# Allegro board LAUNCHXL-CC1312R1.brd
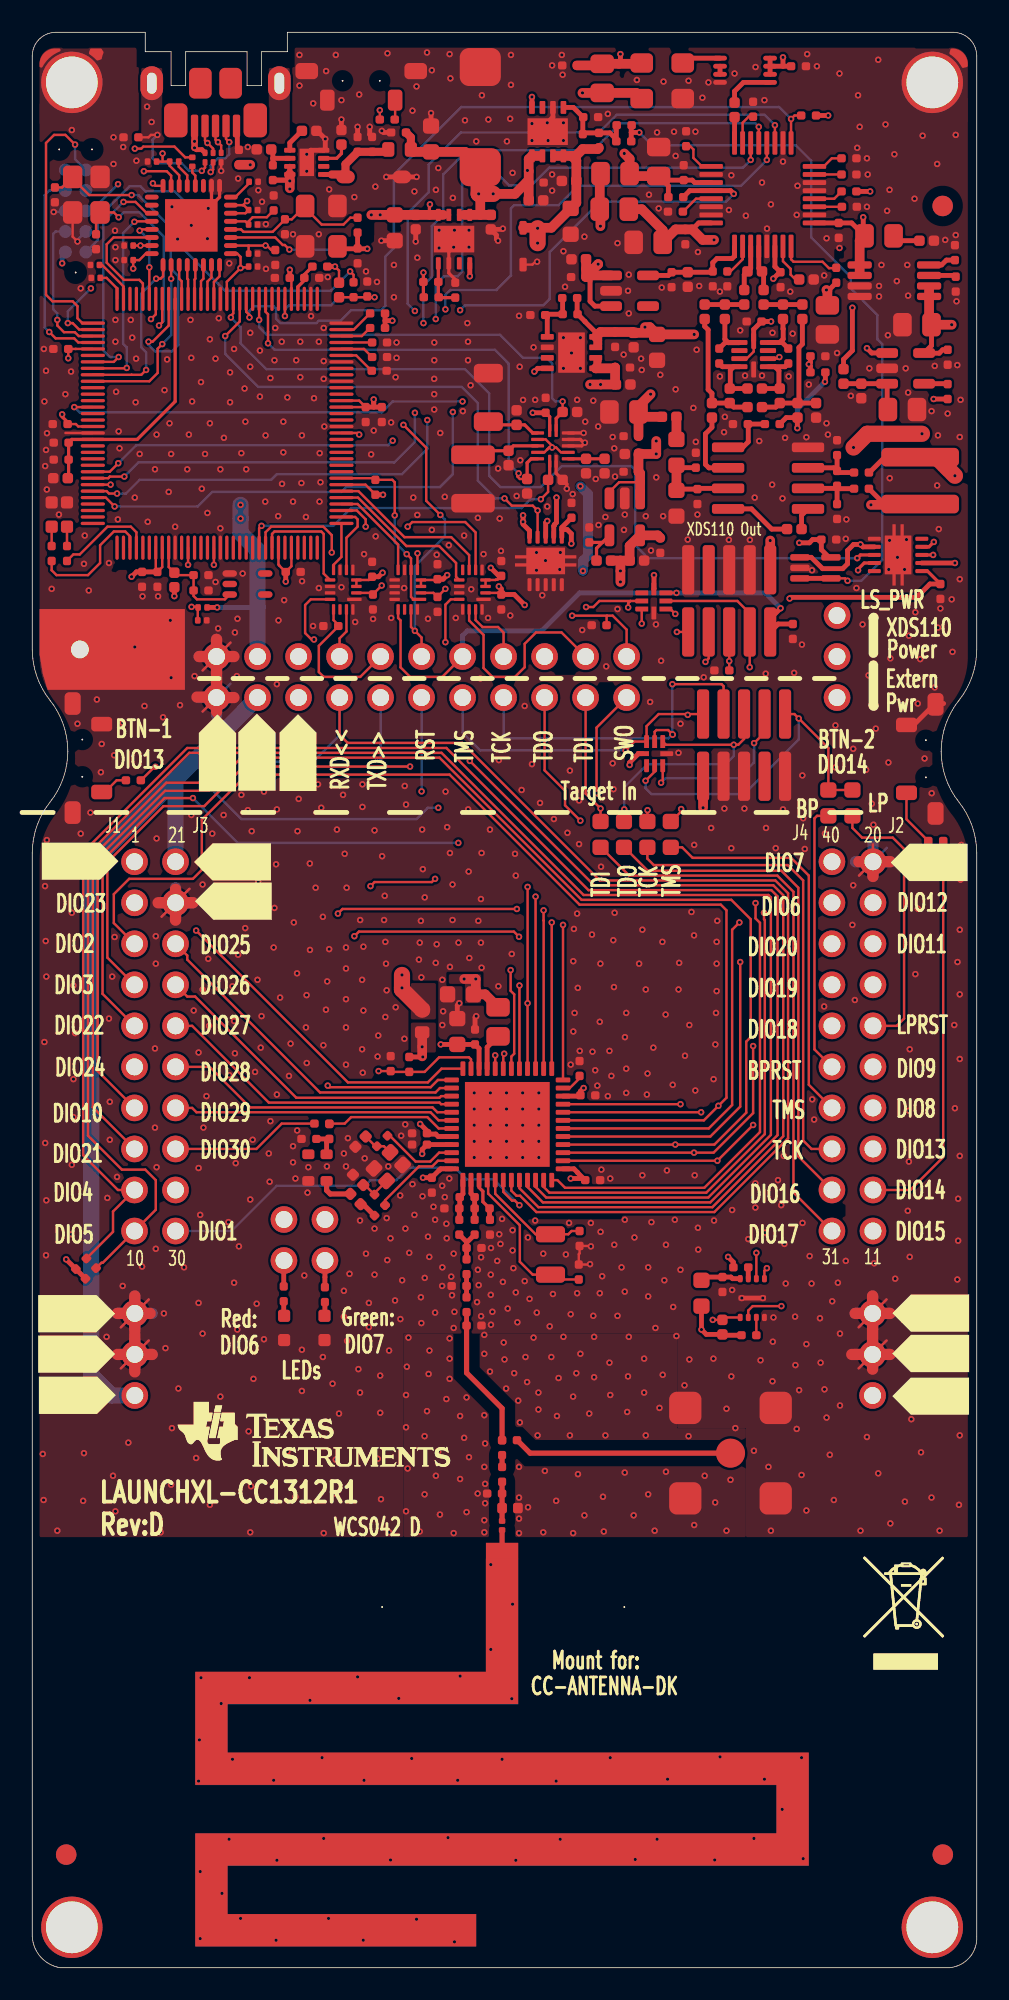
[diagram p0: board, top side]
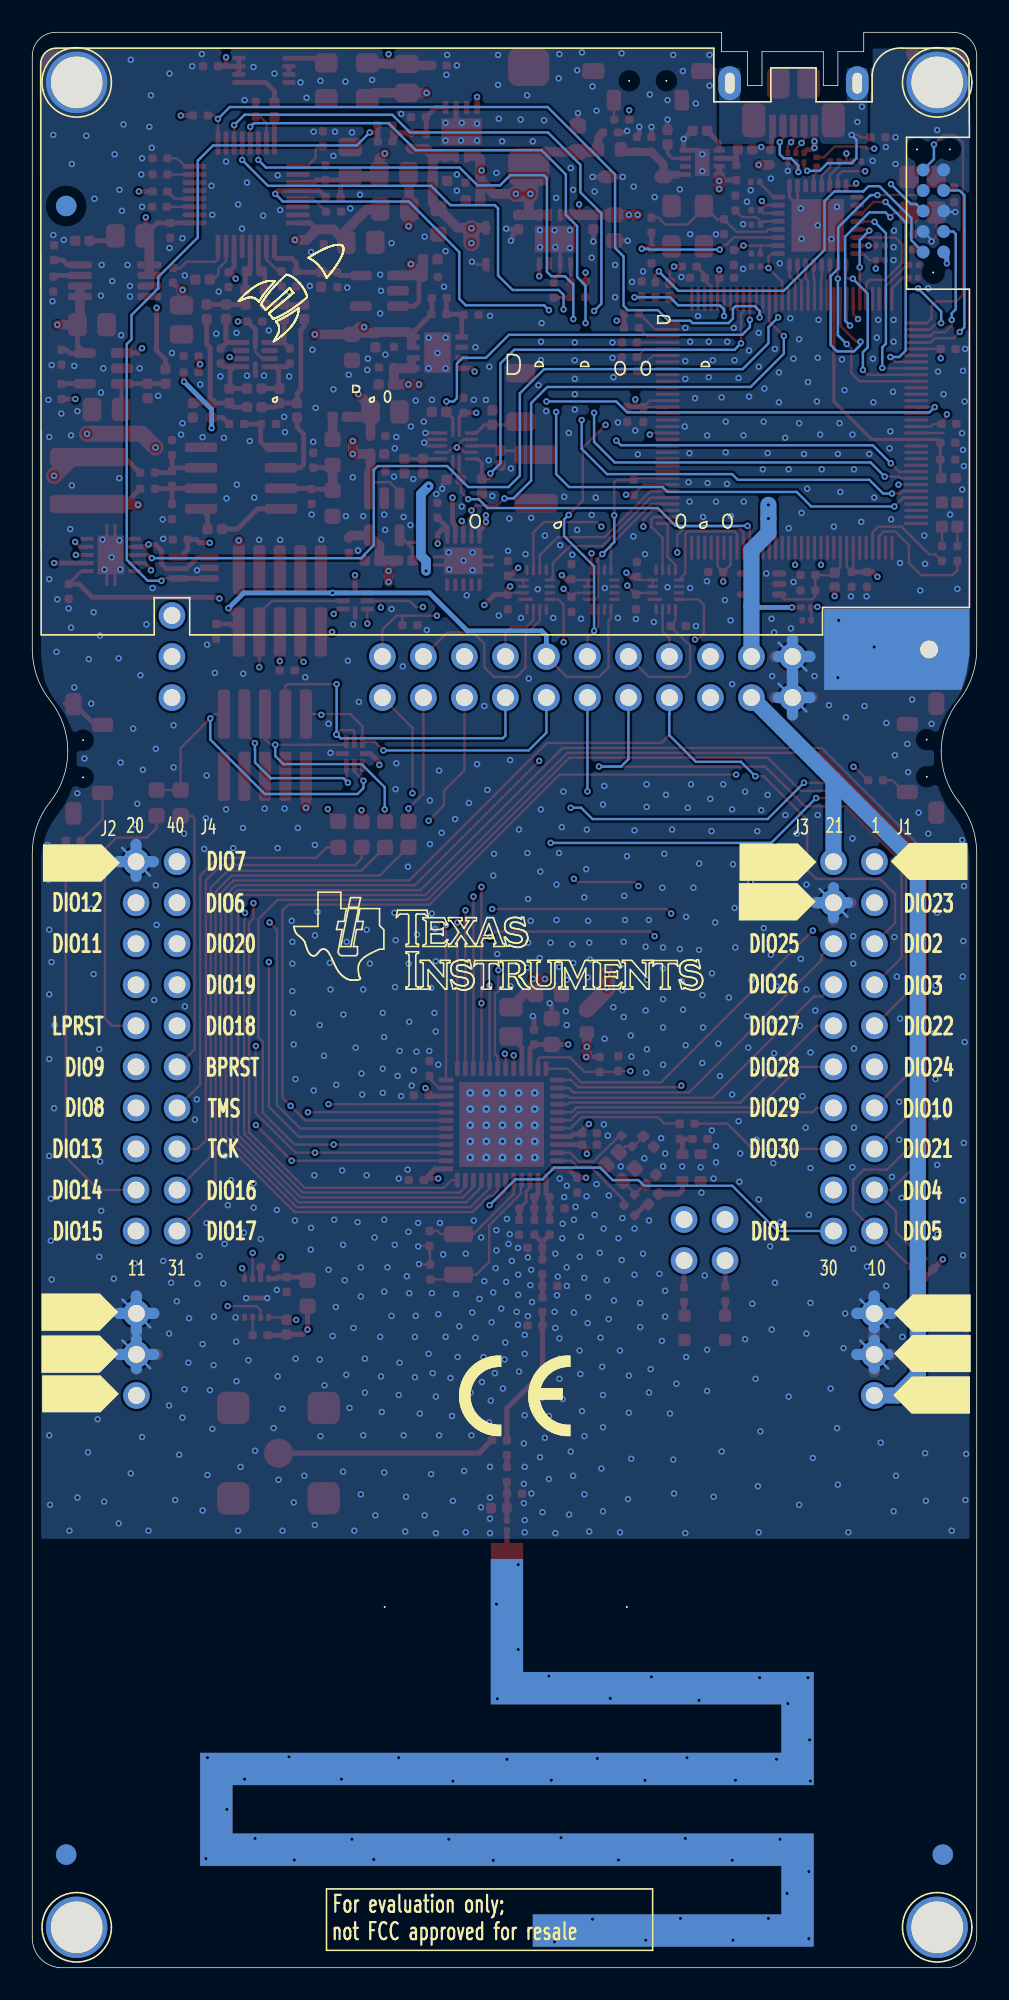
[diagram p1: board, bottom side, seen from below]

Outline 58.5 x 119.8 mm; copper layers: TOP, L2, L3, BOTTOM. Coordinates in mm from the lower left corner of the outline.
Outline path: 0,118.34 0,81.6 arc(0.28,79.93) 1.1,78.45 arc(1.92,76.97) 2.2,75.3 arc(1.92,73.63) 1.1,72.15 arc(0.28,70.67) 0,69 0,1.95 arc(0.51,0.67) 1.72,0 56.8,0 arc(58.05,0.63) 58.5,1.95 58.5,69 arc(58.22,70.67) 57.4,72.15 arc(56.58,73.63) 56.3,75.3 arc(56.58,76.97) 57.4,78.45 arc(58.22,79.93) 58.5,81.6 58.5,118.34 arc(58.07,119.37) 57.04,119.8 15.8,119.8 15.8,118.6 14.2,118.6 14.2,116.5 13.3,116.5 13.3,118.6 9.5,118.6 9.5,116.5 8.6,116.5 8.6,118.6 7,118.6 7,119.8 1.46,119.8 arc(0.43,119.37) 0,118.34

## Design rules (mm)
constraint set DEFAULT: min track width 0.15
nets with their own width: min track width 0.15; nets GND VDDR VDDS WMCU_VDD

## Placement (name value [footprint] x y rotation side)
A1  DNM  [ANTENNA_DN024N]  29.1 25.8 180 top
C1  12pF  [CAPC1005X60B2N]  3.95 107.3 270 top
C2  10nF  [CAPC1005X60B2N]  15.7 86.4 0 top
C3  10nF  [CAPC1005X60B2N]  2.19 95.55 180 top
C4  10nF  [CAPC1005X60B2N]  2.23 100.2 180 top
C6  100nF  [CAPC0603X35B2N]  13.4 105.3 0 top
C7  10nF  [CAPC1005X60B2N]  6.8 86.4 270 top
C8  0.1uF  [CAPC1005X60B2N]  9.99 86.2 0 top
C9  12pF  [CAPC1005X60B2N]  1.4 110.2 270 top
C11  3.6pF  [CAPC1005X60B2N]  26.45 47 180 top
C12  0.1uF  [CAPC1005X60B2N]  34.25 48.75 0 top
C14  0.1uF  [CAPC1005X60B2N]  33.95 54 0 top
C15  0.1uF  [CAPC1005X60B2N]  24.45 51.65 180 top
C16  22uF  [CAPC1608X100A2N]  26.32 57.15 90 top
C17  0.1uF  [CAPC1005X60B2N]  27.42 57.15 90 top
C18  22uF  [CAPC1608X100A2N]  27.32 60.25 180 top
C19  0.1uF  [CAPC1005X60B2N]  24.45 50.95 180 top
C20  0.1uF  [CAPC1005X60B2N]  24.75 48.9 270 top
C21  3.6pF  [CAPC1005X60B2N]  27.4 46.3 270 top
C22  DNM  [CAPC1005X60A2N]  20.5 48.45 135 top
C23  DNM  [CAPC1005X60A2N]  20.65 51.45 225 top
C24  0.1uF  [CAPC1005X60B2N]  17.6 51.3 180 top
C25  1nF  [CAPC1005X60A2N]  19.7 47.9 315 top
C30  0.1uF  [CAPC1005X60B2N]  42.75 42.75 270 top
C31  100pF  [CAPC1005X60B2N]  28.35 46.3 270 top
C33  2.7pF  [CAPC1005X60B2N]  26.9 44.55 0 top
C34  6.2pF  [CAPC1005X60B2N]  26.9 42.2 180 top
C35  3pF  [CAPC1005X60B2N]  26.9 39.75 0 top
C36  100pF  [CAPC1005X60B2N]  29.1 32.65 270 top
C37  DNM  [CAPC1005X60B2N]  29.1 32.65 0 top
C38  0.1uF  [CAPC1005X60B2N]  15.95 104.6 180 top
C39  0.1uF  [CAPC1005X60B2N]  20.65 96.6 270 top
C40  1uF  [CAPC1005X60B2N]  21.65 96.6 270 top
C41  12pF  [CAPC1005X60B2N]  33.85 42.6 90 top
C42  1uF  [CAPC1005X60B2N]  7.75 86.4 270 top
C43  0.1uF  [CAPC1005X60B2N]  2.25 94.4 180 top
C44  1uF  [CAPC1005X60B2N]  2.25 93.35 180 top
C45  2.2uF  [CAPC1005X60A2N]  2.2 92.2 180 top
C46  0.1uF  [CAPC1005X60B2N]  16.85 104.6 0 top
C47  15pF  [CAPC1005X60B2N]  24.25 103.4 0 top
C48  2.2uF  [CAPC1005X60A2N]  28.4 108.5 270 top
C49  2.2uF  [CAPC1005X60A2N]  23.75 108.5 270 top
C50  10nF  [CAPC1005X60B2N]  9.99 85.25 0 top
C51  15pF  [CAPC1005X60B2N]  33.9 45.6 270 top
C52  0.1uF  [CAPC1005X60B2N]  22.2 55.5 90 top
C53  1uF  [CAPC1005X60B2N]  33.9 55.2 90 top
C70  0.1uF  [CAPC1005X60B2N]  21.1 85 270 top
C71  0.1uF  [CAPC1005X60B2N]  21.05 86.1 90 top
C72  0.1uF  [CAPC1005X60B2N]  29.05 85 270 top
C73  0.1uF  [CAPC1005X60B2N]  29.05 86.15 90 top
C74  0.1uF  [CAPC1005X60B2N]  25.1 84.85 270 top
C75  0.1uF  [CAPC1005X60B2N]  25.1 85.95 90 top
C78  100nF  [CAPC0603X35B2N]  6.25 105.7 180 top
C79  100nF  [CAPC0603X35B2N]  13.4 108.8 0 top
C80  100nF  [CAPC0603X35B2N]  7.7 111.8 180 top
C83  100nF  [CAPC0603X35B2N]  13.4 106.1 0 top
C84  100nF  [CAPC0603X35B2N]  6.25 106.6 180 top
C85  4.7uF  [CAPC1005X60B2N]  15.05 105.4 90 top
C86  4.7uF  [CAPC1005X60B2N]  14.95 109.7 270 top
C87  100nF  [CAPC0603X35B2N]  13.4 107.9 0 top
C88  12pF  [CAPC1005X60B2N]  15.65 107.3 90 top
C89  12pF  [CAPC1005X60B2N]  20.15 105.5 90 top
C106  0.1uF  [CAPC1005X60B2N]  12.8 111.6 90 top
C107  33nF  [CAPC1005X60A2N]  16.7 113.7 0 top
C108  10nF  [CAPC1005X60B2N]  21.05 112.4 90 top
C109  1uF  [CAPC1005X60B2N]  20.15 112.4 90 top
C110  0.1uF  [CAPC1005X60B2N]  23.15 113.6 180 top
C111  3.3uF  [CAPC1608X90A2N]  24.7 114 270 top
C112  220uF  [CAPMP7343X430A2N]  27.75 111.45 90 top
C113  22uF  [CAPC1608X100A2N]  22.45 108.5 270 top
C114  0.1uF  [CAPC1005X60B2N]  56.25 85.65 270 top
C115  0.1uF  [CAPC1005X60B2N]  47 117.7 0 top
C116  0.1uF  [CAPC1005X60B2N]  40.35 110.65 90 top
C117  10uF  [CAPC2012X150A2N]  38.8 110.9 90 top
C118  0.1uF  [CAPC1005X60B2N]  33.75 117.75 180 top
C119  0.1uF  [CAPC1005X60B2N]  40.45 107.6 270 top
C120  0.1uF  [CAPC1005X60B2N]  46.35 104.95 270 top
C121  10uF  [CAPC2012X150A2N]  39.05 106.8 180 top
C122  10uF  [CAPC2012X150A2N]  49.25 102.9 270 top
C123  270pF  [CAPC1005X60B2N]  42.55 99.3 90 top
C124  DNM  [CAPC1005X60B2N]  49.85 94.55 270 top
C125  0.1uF  [CAPC1005X60B2N]  41.2 90.6 90 top
C126  0.1uF  [CAPC1005X60B2N]  44.25 101.9 0 top
C127  0.1uF  [CAPC1005X60B2N]  49.95 108 270 top
C128  1uF  [CAPC1005X60B2N]  42.15 105 270 top
C129  470pF  [CAPC1005X60A2N]  44.3 96.6 0 top
C130  1nF  [CAPC1005X60A2N]  44.3 97.75 0 top
C131  22nF  [CAPC1005X60A2N]  44.3 105 0 top
C132  DNM  [CAPC1005X60B2N]  49.85 92.65 270 top
C133  1uF  [CAPC1005X60B2N]  48.2 99.75 0 top
C134  DNM  [CAPC1005X60B2N]  49.85 90.6 270 top
C135  270pF  [CAPC1005X60B2N]  46.83 99.3 90 top
C136  1uF  [CAPC1005X60B2N]  43.05 105 270 top
C137  1uF  [CAPC1005X60B2N]  50.15 109 0 top
C138  1uF  [CAPC1005X60B2N]  40.5 112.75 90 top
C139  0.1uF  [CAPC1005X60B2N]  33.4 89.75 90 top
C140  0.1uF  [CAPC1005X60B2N]  31.8 96.25 90 top
C141  0.1uF  [CAPC1005X60B2N]  56.7 100.15 270 top
C142  10uF  [CAPC2012X150A2N]  55.7 101.7 180 top
C143  2.2uF  [CAPC1005X60A2N]  30 95.5 90 top
C144  2.2uF  [CAPC1005X60A2N]  29.5 93.9 270 top
C145  1uF  [CAPC1005X60B2N]  57.15 105.7 90 top
C146  47uF  [CAPC2012X150A2N]  51.55 107.2 0 top
C147  10uF  [CAPC2012X150A2N]  53 96.45 0 top
C149  2.2uF  [CAPC1005X60A2N]  34.3 93.4 270 top
C151  2.2uF  [CAPC1005X60A2N]  36.15 98 0 top
C152  0.1uF  [CAPC1005X60B2N]  36.1 99.05 0 top
C153  15pF  [CAPC1005X60B2N]  33.75 103.35 180 top
C154  0.1uF  [CAPC1005X60B2N]  36.1 101.25 270 top
C155  2.2uF  [CAPC1005X60A2N]  37.25 101.2 270 top
C156  22uF  [CAPC1608X100A2N]  38.7 101.1 270 top
C157  2.2uF  [CAPC1005X60A2N]  34.3 105.75 180 top
C158  0.1uF  [CAPC1005X60B2N]  39.6 104.95 270 top
C159  2.2uF  [CAPC1005X60A2N]  40.6 104.95 270 top
C160  2.2uF  [CAPC1005X60A2N]  37.6 93.7 180 top
C161  0.1uF  [CAPC1005X60B2N]  37.55 92.6 180 top
C162  0.1uF  [CAPC1005X60B2N]  38.9 88.5 270 top
C163  2.2uF  [CAPC1005X60A2N]  37 87.1 0 top
C164  0.1uF  [CAPC1005X60B2N]  34.3 104.65 180 top
C165  10uF  [CAPC2012X150A2N]  37.55 96.3 180 top
C166  10nF  [CAPC1005X60B2N]  37.55 94.8 180 top
C167  0.1uF  [CAPC1005X60B2N]  41.1 92.85 90 top
C168  22uF  [CAPC1608X100A2N]  39.9 91.45 270 top
C169  DNM  [CAPC1005X60B2N]  36.2 114.05 0 top
C170  DNM  [CAPC1005X60B2N]  49.8 88.4 180 top
C171  2.2uF  [CAPC1005X60A2N]  30.75 109.4 0 top
C172  15pF  [CAPC1005X60B2N]  35.1 112.65 90 top
C173  2.2uF  [CAPC1005X60A2N]  33.7 110.6 180 top
C174  22uF  [CAPC1608X100A2N]  33.35 108.9 270 top
C175  0.1uF  [CAPC1005X60B2N]  30.75 110.5 0 top
CR1  LPL296-J2L2-25  [LEDC1707X65N]  18.1 38.85 90 top
CR2  LS L296-P2Q2-1  [LEDC1708X67N]  15.6 38.85 90 top
CR4  LS L296-P2Q2-1  [LEDC1708X67N]  1.2 90.7 270 top
CR5  LPL296-J2L2-25  [LEDC1707X65N]  2.15 90.7 270 top
CR6  TPD4E004DRY  [SON50P100X145X60-6B2N]  10.7 111.75 0 top
CR7  TPD6E004RSER  [QFN50P150X150X60-8N]  37.75 85.1 270 top
CR8  TPD6E004RSER  [QFN50P150X150X60-8N]  38.05 74.4 0 top
CR14  DNM  [SODFL2512X80A2N]  30.4 107.7 270 top
CR15  NRVB130T1G  [SOD3716X135N]  19.4 110.85 0 top
FIDU1  DNM  [FID127X142]  56.39 109.05 0 top
FIDU2  DNM  [FID127X142]  2.1 7 0 top
FIDU3  DNM  [FID127X142]  56.4 7 0 top
FIDU4  DNM  [FID127X142]  56.4 109.05 180 bottom
FIDU5  DNM  [FID127X142]  2.1 7 180 bottom
FIDU6  DNM  [FID127X142]  56.4 7 180 bottom
FL1  BLM18HE152SN1  [FIL_BLM18HE152SN1DN]  24.15 57.9 90 top
FL2  BLM18HE152SN1  [FIL_BLM18HE152SN1DN]  23.45 112.55 180 top
FL3  BLM18HE152SN1  [FIL_BLM18HE152SN1DN#2]  39.9 93 90 top
FL4  BLM21PG221SN1  [FILC2012X110A2N]  35.3 116.05 90 top
FL5  BLM21PG221SN1  [FILC2012X110A2N]  35.2 111.05 0 top
FL6  BLM21PG221SN1  [FILC2012X110A2N]  36.95 108.85 180 top
J1  SSQ-110-23-L-D  [SAMTEC_SSQ11023LD_A2B]  6.33 68.46 0 bottom
J2  SSQ-110-23-L-D  [SAMTEC_SSQ11023LD_A2B]  49.53 68.46 0 bottom
J6  105164-0001  [MOLEX_1051640001_B2N]  10.05 114 0 top
J7  SMA-10V21-TGG  [HUSTSAN_SMA10V21TGGAN]  43.25 31.85 0 top
L10  6.8uH  [INDC2012X150A2N]  28.85 57.65 90 top
L11  7.5nH  [INDC1005X60D2N]  26.45 46.3 270 top
L12  27nH  [INDC1005X60D2N]  27.4 47.7 180 top
L32  7.5nH  [INDC1005X60D2N]  27.4 47 0 top
L33  6.8nH  [INDC1005X60D2N]  26.9 43.85 270 top
L34  6.8nH  [INDC1005X60D2N]  26.9 41.5 270 top
LBL1  CE_label  [CE_MARKING]  29.45 32.9 180 bottom
LBL2  DNM  [TI_LOGO_1]  10 35.03 0 top
LBL4  DNM  [LABEL_FOR_EVALUATION_ONLY]  40.12 1.22 180 bottom
LBL6  TRASH_7mm  [TRASH_7MM]  52.1 18.45 0 top
M1  SNT-100-BK-G  [SAMTEC_SNT100BKG]  16.88 42.5 90 top
M2  SNT-100-BK-G  [SAMTEC_SNT100BKG]  19.38 42.5 90 top
M3  SNT-100-BK-G  [SAMTEC_SNT100BKG]  12.65 77.3 90 top
M4  SNT-100-BK-G  [SAMTEC_SNT100BKG]  15.25 77.3 90 top
M5  SNT-100-BK-G  [SAMTEC_SNT100BKG]  17.75 77.3 90 top
M6  SNT-100-BK-G  [SAMTEC_SNT100BKG]  20.25 77.3 90 top
M7  SNT-100-BK-G  [SAMTEC_SNT100BKG]  22.85 77.3 90 top
M8  SNT-100-BK-G  [SAMTEC_SNT100BKG]  25.35 77.3 90 top
M9  SNT-100-BK-G  [SAMTEC_SNT100BKG]  27.95 77.3 90 top
M10  SNT-100-BK-G  [SAMTEC_SNT100BKG]  30.45 77.3 90 top
M11  SNT-100-BK-G  [SAMTEC_SNT100BKG]  33.05 77.3 90 top
M12  SNT-100-BK-G  [SAMTEC_SNT100BKG]  35.55 77.3 90 top
M13  SNT-100-BK-G  [SAMTEC_SNT100BKG]  38.15 77.3 90 top
M14  SNT-100-BK-G  [SAMTEC_SNT100BKG]  51.15 79.9 90 top
M15  DCB-10  [MECH_DCB10_A2B]  4.15 4.05 180 bottom
M16  DCB-10  [MECH_DCB10_A2B]  54.5 4 180 bottom
M17  DCB-10  [MECH_DCB10_A2B]  4.25 115 180 bottom
M18  DCB-10  [MECH_DCB10_A2B]  54 114.95 180 bottom
MH1  DNM  [MTG320_380]  2.45 2.5 180 bottom
MH2  DNM  [MTG320_380]  55.75 2.5 180 bottom
MH3  DNM  [MTG320_380]  2.45 116.7 180 bottom
MH4  DNM  [MTG320_380]  55.75 116.7 180 bottom
MH5  DNM  [MTG110_170]  2.95 81.6 0 top
NOREF  -  []  -4.35 67.3 0 top
NOREF#2  -  []  51.55 38.1 0 top
NOREF#3  -  []  -178.4 -140.5 0 top
NOREF#4  -  []  -2.05 32.9 0 top
NOREF#5  -  []  51.45 66 0 top
NOREF#6  -  []  8.35 63.6 0 top
NOREF#7  -  []  -1.95 38.1 0 top
NOREF#8  -  []  -70.48 81.55 0 top
NOREF#9  -  []  -59.23 124.59 0 top
NOREF#10  -  []  56.3 75.34 0 top
NOREF#11  -  []  -1.95 35.6 0 top
NOREF#12  #VALUE  [unnamed#2]  21.67 22.32 0 top
NOREF#13  -  []  -75.31 -10.05 90 top
NOREF#14  -  []  17.65 67.9 90 top
NOREF#15  -  []  58.03 0.61 0 top
NOREF#16  -  []  53.05 34 0 top
NOREF#17  -  []  52.06 0 90 top
NOREF#18  -  []  0.85 -28.78 0 top
NOREF#19  -  []  8.35 65.9 0 top
NOREF#20  -  []  -73.08 125.52 0 top
NOREF#21  -  []  51.55 35.6 0 top
NOREF#22  -  []  16.45 70.4 90 top
NOREF#23  -  []  0 112.17 0 top
NOREF#24  -  []  33.55 35.5 0 top
NOREF#25  -  []  13.85 70.5 90 top
NOREF#26  -  []  6.85 32.9 180 bottom
NOREF#27  -  []  6.85 35.6 180 bottom
NOREF#28  -  []  5.55 67.1 180 bottom
NOREF#29  -  []  6.85 38.1 180 bottom
NOREF#30  -  []  17.05 63.6 180 bottom
NOREF#31  -  []  17.15 65.9 180 bottom
NOREF#32  -  []  51.48 89.52 180 bottom
NOREF#33  -  []  57.95 34.3 180 bottom
NOREF#34  -  []  60.25 38.2 180 bottom
NOREF#35  -  []  60.15 66 180 bottom
NOREF#36  -  []  60.25 35.6 180 bottom
P1  BB02-HC031-KB1-603000  [GRADCONN_BB02HC031KB1603000_A2B]  52.05 35.42 90 top
P2  BB02-HC031-KB1-603000  [GRADCONN_BB02HC031KB1603000_A2B]  6.35 35.42 90 top
P4  BB02-HJ221-KB1-603000  [GRADCONN_BB02HJ221KB160300_A2B]  36.81 81.16 180 top
P5  FTSH-105-01-F-DV-K  [SAMTEC_FTSH10501FDVK_A2N]  41.55 73.75 0 top
P6  BB02-HJ041-KB1-603000  [GRADCONN_BB02HJ041KB1603000_A2B]  15.59 43.77 0 top
P7  FTSH-105-01-F-DV-K  [SAMTEC_FTSH10501FDVK_A2N]  45.71 86.53 180 top
P8  DNM  [TAGCONNECT_TC2050IDCNL_A2N]  2.05 106.2 90 bottom
P10  BB02-HC031-KB1-603000  [GRADCONN_BB02HC031KB1603000_A2B]  49.85 83.7 270 top
PCB1  As Per Fab Drawing-WCS042  [TI_MCUXX]  54.25 30.35 0 top
R1  100k  [RESC1005X40B2N]  23.35 55.45 90 top
R2  3.3k  [RESC1005X40B2N]  3.35 43.9 225 top
R3  3.3k  [RESC1005X40B2N]  3.95 43.3 225 top
R5  0  [RESC1005X40B2N]  21.85 47.2 135 top
R6  0  [RESC1005X40B2N]  22 51.5 225 top
R7  DNM  [RESC1005X40B2N]  21.2 46.55 45 top
R8  DNM  [RESC1005X40B2N]  18.4 51.3 90 top
R9  0  [RESC1005X40B2N]  18.4 52.25 180 top
R11  2.2k  [RESC1005X40A2N]  42.75 39.2 90 top
R12  0  [RESC1608X55A2N]  41.45 42.55 270 top
R14  220  [RESC1005X40B2N]  15.57 41.25 90 top
R15  180  [RESC1005X40B2N]  18.12 41.2 90 top
R17  10k  [RESC1005X40A2N]  19 103.4 90 top
R18  4.7k  [RESC1005X40A2N]  8.8 86.35 270 top
R20  100  [RESC1005X40B2N]  19.9 103.4 90 top
R21  DNM  [RESC1005X40B2N]  20.75 103.45 90 top
R23  180  [RESC1005X40B2N]  1.2 88 270 top
R25  220  [RESC1005X40B2N]  2.15 88 270 top
R27  1k  [RESC1005X40B2N]  21.85 101.5 180 top
R28  4.87k  [RESC1005X40B2N]  21.95 98.85 180 top
R29  1k  [RESC1005X40B2N]  21.05 100.6 0 top
R30  1k  [RESC1005X40B2N]  21.05 99.7 0 top
R31  51  [RESC1005X40B2N]  17.35 105.3 0 top
R32  33k  [RESC1005X40B2N]  5.65 113.3 0 top
R33  51k  [RESC1005X40B2N]  25.15 104.35 180 top
R34  30k  [RESC1005X40B2N]  26.2 104.3 270 top
R39  1k  [RESC1005X40B2N]  21.85 102.4 180 top
R46  DNM  [RESC1608X55A2N]  39.55 69.35 90 top
R47  DNM  [RESC1608X55A2N]  38.1 69.35 90 top
R48  0  [RESC1608X55A2N]  36.65 69.35 90 top
R49  0  [RESC1608X55A2N]  35.2 69.35 90 top
R51  0  [RESC1608X55A2N]  50.8 71.3 90 top
R52  0  [RESC1608X55A2N]  49.31 71.3 90 top
R55  100  [RESC1005X40B2N]  55.5 69.75 0 top
R56  100  [RESC1005X40B2N]  5.8 73.5 0 top
R57  100  [RESC1005X40B2N]  22.45 114.4 180 top
R58  3.3k  [RESC1005X40B2N]  21.25 92.1 270 top
R59  DNM  [RESC1005X40B2N]  44.85 39.15 180 top
R60  DNM  [RESC1005X40B2N]  44.35 43.35 180 top
R61  100k  [RESC1005X40B2N]  18.03 83.05 0 top
R62  100k  [RESC1005X40B2N]  34.65 83.1 0 top
R63  100k  [RESC1005X40B2N]  42.25 80.3 0 top
R65  100k  [RESC1005X40B2N]  47.11 82.25 90 top
R82  10k  [RESC0603X35B2N]  9.91 111.5 90 top
R83  10k  [RESC0603X35B2N]  8.51 111.8 0 top
R84  12k  [RESC0603X35B2N]  13.99 110.55 180 top
R87  1M  [RESC1005X40B2N]  20.15 107.4 90 top
R90  1k  [RESC0603X35B2N]  3.6 105.4 0 top
R91  1k  [RESC0603X35B2N]  3.65 104.6 0 top
R92  10k  [RESC0603X35B2N]  10.27 84.2 0 top
R93  20k  [RESC0603X35B2N]  10.25 83.4 0 top
R94  22  [RESC1005X40A2N]  43.5 114.55 90 top
R95  1.2k  [RESC1005X40A2N]  41.65 102.95 270 top
R96  100k  [RESC1005X40B2N]  48.55 114.65 180 top
R97  100k  [RESC1005X40B2N]  40.3 108.7 180 top
R98  100k  [RESC1005X40B2N]  49.8 104.3 90 top
R99  0  [RESC1005X40B2N]  50.9 92.55 0 top
R100  0  [RESC1005X40B2N]  46.3 95.55 180 top
R101  1.2k  [RESC1005X40A2N]  42.1 96.85 270 top
R102  330  [RESC1005X40A2N]  43.2 97.75 270 top
R103  4.99  [RESC1005X40A2N]  42.9 102.95 270 top
R104  10  [RESC1005X40A2N]  44.1 103.85 270 top
R105  100k  [RESC1005X40B2N]  44.65 115.5 270 top
R106  DNM  [RESC1005X40B2N]  43.4 95.55 0 top
R107  1  [RESC3246X70A2N]  55 93.5 270 top
R108  0  [RESC1005X40B2N]  50.9 91.55 0 top
R109  1.2k  [RESC1005X40A2N]  47.4 96.85 270 top
R110  330  [RESC1005X40A2N]  46.3 97.75 270 top
R111  DNM  [RESC1005X40B2N]  48.2 98.75 0 top
R112  4.99  [RESC1005X40A2N]  46.5 102.95 270 top
R113  10  [RESC1005X40A2N]  45.3 103.85 270 top
R114  100k  [RESC1005X40B2N]  39.4 109.6 0 top
R115  DNM  [RESC1005X40A2N]  48.55 96.85 270 top
R116  60.4k  [RESC1005X40A2N]  48.4 104.5 180 top
R117  100k  [RESC1005X40B2N]  51.05 112 180 top
R118  100k  [RESC1005X40B2N]  51.05 111 180 top
R119  100k  [RESC1005X40B2N]  51.05 109.95 180 top
R120  1.2k  [RESC1005X40A2N]  47.7 102.95 270 top
R121  22k  [RESC1005X40A2N]  50.25 98.95 270 top
R122  0.22  [RESC1005X50A2N]  55.85 106.9 180 top
R123  82  [RESC3216X75A2N]  28.25 98.7 270 top
R125  36.5  [RESC3225X75A2N]  27.3 90.65 90 top
R126  4.7k  [RESC1005X40A2N]  51.35 97.15 90 top
R127  47k  [RESC1005X40A2N]  31.95 92.1 0 top
R128  47k  [RESC1005X40A2N]  30.65 92.15 270 top
R129  47k  [RESC1005X40A2N]  32.85 96.3 0 top
R130  2.2k  [RESC1005X40A2N]  35.45 93.4 270 top
R131  0  [RESC1005X40B2N]  56.7 97.1 90 top
R132  51k  [RESC1005X40B2N]  32.85 102.35 0 top
R133  30k  [RESC1005X40B2N]  30.85 102.3 0 top
R134  60.4k  [RESC1005X40A2N]  34.95 87.1 0 top
R135  30k  [RESC1005X40B2N]  34.5 89.15 270 top
R136  100k  [RESC1005X40B2N]  57.2 103.75 90 top
R137  2.61k  [RESC1005X40A2N]  46.75 89.05 0 top
R138  DNM  [RESC1005X40B2N]  37.1 113.05 180 top
R151  51k  [RESC1005X40B2N]  34.1 113.5 270 top
R152  30k  [RESC1005X40B2N]  35.05 114.55 180 top
R153  10  [RESC1005X40A2N]  39.9 96 180 top
R154  1M  [RESC1005X40B2N]  14.9 110.65 90 top
R155  390k  [RESC1005X40A2N]  13.9 112.55 0 top
R156  4.7k  [RESC1005X40A2N]  19.15 113.75 270 top
SW1  1188E-1K2  [SW_1188E1K2V_A2N]  2.5 78.25 270 top
SW2  1188E-1K2  [SW_1188E1K2V_A2N]  55.95 71.45 90 top
SW3  1188E-1K2  [SW_1188E1K2V_A2N]  23.75 117.4 180 top
U1  CC1312R1F3RGZ  [QFNFC50P700X700X100-49A2N]  26.67 48.75 0 top
U4  MX25R8035FZUIL0  [SON50P300X200X60-9B2N]  43.85 40.25 0 top
U5  TM4C1294NCPDTT3R  [QFP40P1600X1600X120-128N]  5.25 87.9 0 top
U6  LM4040B25IDCK  [SOT65P210X110-5N]  12.23 86.3 270 top
U7  TPS79601DR  [SON65P300X300X100-9AN]  27.1 108.5 180 top
U8  SN74AVC4T245RSV  [QFNFC40P180X260X55-16A2N]  19.95 84.7 90 top
U9  SN74AVC4T245RSV  [QFNFC40P180X260X55-16A2N]  27.95 84.7 90 top
U10  SN74AVC4T245RSV  [QFNFC40P180X260X55-16A2N]  23.95 84.7 90 top
U15  USB3300-EZK  [QFNWB50P500X500X100-33N]  11.6 110.3 180 top
U33  TS3A24159DRC  [SON50P300X300X100-11A2N]  55.1 86.45 90 top
U34  SN74LVC2G74DCU  [SOP50P310X90-8N]  42.6 118.2 270 top
U35  ADS127L01IPBS  [QFP50P700X700X120-32A2N]  43.5 106.55 0 top
U36  INA118UB  [SOIC127P600X175-8A2N]  48.05 90.3 90 top
U37  THS4551IRUN  [QFNFCP50P200X200X80-10A2N]  43.8 100.6 270 top
U38  TS3A24159DRC  [SON50P300X300X100-11A2N]  32.8 88.55 180 top
U39  TS3A4751RUCR  [QFNFC40P200X200X40-14A2N]  31.3 95 270 top
U40  REF6025IDGK  [SOP65P490X110-8A2N]  55.55 103.45 90 top
U41  OPA320AIDBV  [SOT95P280X145-5A2N]  52.95 99.95 270 top
U42  TPS79601DR  [SON65P300X300X100-9AN]  34.9 99 90 top
U43  LP5907MFX-1.8  [SOT95P280X145-5A2N]  35.85 104.75 270 top
U44  TPS73101DBV  [SOT95P280X145-5A2N]  37.65 90.95 180 top
U45  DNM  [SOT65P210X110-5A2N]  47.55 87.3 270 top
U46  TPS79601DR  [SON65P300X300X100-9AN]  30.95 112.15 0 top
U47  TPS259530DSG  [SON50P200X200X80-9A2N]  15.95 112.5 270 top
Y1  32.768kHz  [XTAL_FC135_A2N]  32.1 42.9 90 top
Y2  48MHz  [OSCCC200X160X45-4A2N]  21.95 48.7 45 top
Y3  16MHz  [OSCCC250X320X100-4BN]  2.5 110.85 270 top
Y4  24MHz  [OSCCC250X320X70-4AN]  16.9 109.05 270 top
Y6  16.384MHz  [OSCSC254P320X500X130-4A2N]  37.75 115.7 0 top
Y7  48MHz  [OSC_TG2016SMN_A2N]  17.1 50.35 270 top
Z60  3.3nH  [INDC1005X60B2N]  29.1 31 270 top
Z61  DNM  [CAPC1005X60B2N]  29.1 29.35 180 top
Z62  DNM  [IND_LQW15AN]  29.1 28.45 0 top
Z63  5.6pF  [CAPC0603X35B2N]  29.1 27.65 270 top

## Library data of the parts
A1 = ANTENNA_PCB_0: User Part Number: #PN
C1-C4 C7-C9 C11 C12 C14 C15 C17 C19-C21 C24 C30 C31 C33-C39 C41 C43 C46 C47 C50-C52 C70-C75 C85 C86 C88 C89 C106 C108 C110 C114-C116 C118-C120 C123-C127 C132 C134 C135 C139-C141 C152-C154 C158 C161 C162 C164 C166 C167 C169 C170 C172 C175 Z61 = CAPACITOR: User Part Number: #PN
C6 C78-C80 C83 C84 C87 Z63 = CAPACITOR: User Part Number: #PN; alternate symbols: (CAPC0603X35B2L,CAPC0603X35B2M)
C16 C18 C113 C156 C168 C174 = CAPACITOR: User Part Number: #PN; alternate symbols: (CAPC1608X100A2L,CAPC1608X100A2M)
C22 C23 C25 C40 C42 C44 C45 C48 C49 C53 C107 C109 C128-C131 C133 C136-C138 C143-C145 C149 C151 C155 C157 C159 C160 C163 C171 C173 = CAPACITOR: User Part Number: #PN; alternate symbols: (CAPC1005X60A2L,CAPC1005X60A2M)
C111 = CAPACITOR: User Part Number: #PN; alternate symbols: (CAPC1608X90A2L,CAPC1608X90A2M)
C112 = CAPACITOR_POL_8: User Part Number: #PN; alternate symbols: (CAPMP7343X430A2L,CAPMP7343X430A2M)
C117 C121 C122 C142 C146 C147 C165 = CAPACITOR: User Part Number: #PN; alternate symbols: (CAPC2012X150A2L,CAPC2012X150A2M)
CR1 CR5 = LED_0: alternate symbols: (LEDC1707X65L,LEDC1707X65M)
CR2 CR4 = LED_0: alternate symbols: (LEDC1708X67L,LEDC1708X67M)
CR6 = DIODE_TVS_TPD4E004_SON6: User Part Number: #PN; alternate symbols: (SON50P100X145X65-6L,SON50P100X145X65-6M)
CR7 CR8 = DIODE_TVS_TPD6E004_QFN8_V1: alternate symbols: (QFN50P150X150X60-8L,QFN50P150X150X60-8M)
CR14 = DIODE_ZENER_1: User Part Number: #PN; alternate symbols: (SODFL2512X80A2L,SODFL2512X80A2M)
CR15 = DIODE_SCHOTTKY_2: alternate symbols: (SOD3716X135L,SOD3716X135M,SOD3716X135BN)
FIDU1-FIDU6 = FIDMARK
FL1-FL3 = FILTER_2PIN: alternate symbols: (FIL_BLM18HE152SN1DL,FIL_BLM18HE152SN1DM)
FL4 = INDUCTOR_3: User Part Number: #PN; alternate symbols: (FILC2012X110A2L,FILC2012X110A2M)
FL5 = INDUCTOR_4: User Part Number: #PN; alternate symbols: (FILC2012X110A2L,FILC2012X110A2M)
FL6 = INDUCTOR_5: User Part Number: #PN; alternate symbols: (FILC2012X110A2L,FILC2012X110A2M)
J1 J2 = CONN_HEADER_2X10_J_S_V1: User Part Number: #PN; alternate symbols: (SAMTEC_SSQ11023LD_A2C,SAMTEC_SSQ11023LD_A2A)
J6 = CONN_USB_MICRO_B_2MH: User Part Number: #PN; alternate symbols: (MOLEX_1051640001_B2L,MOLEX_1051640001_B2M)
J7 = CONN_COAX_1_4: alternate symbols: (HUSTSAN_SMA10V21TGGL,HUSTSAN_SMA10V21TGGM)
L10 = INDUCTOR_4: User Part Number: #PN; alternate symbols: (INDC2012X150A2L,INDC2012X150A2M)
L11 L32-L34 = INDUCTOR_HOR_1_1: User Part Number: #PN
L12 = INDUCTOR_HOR_1_0: User Part Number: #PN
LBL1 = CE_LABEL_V1
LBL2 = TI_LOGO_V1
LBL4 = LABEL_FOR_EVALUATOIN_ONLY: User Part Number: #PN
LBL6 = TRASH_V2: User Part Number: #PN
M1-M14 = MECH_SHUNT_JUMPER_V1: User Part Number: #PN
M15-M18 = MECH_SPACERS_SUPPORT_V1: User Part Number: #PN
MH1-MH5 = HOLE_PTH
NOREF#12 = -: User Part Number: #PN
P1 P2 P10 = CONN_HEADER_3_P_S: User Part Number: #PN; alternate symbols: (GRADCONN_BB02HC031KB1603000_A2C,GRADCONN_BB02HC031KB1603000_A2A)
P4 = CONN_HEADER_2X11_P_S: User Part Number: #PN; alternate symbols: (GRADCONN_BB02HJ221KB160300_A2C,GRADCONN_BB02HJ221KB160300_A2A)
P5 P7 = CONN_HEADER_2X5: User Part Number: #PN; alternate symbols: (SAMTEC_FTSH10501FDVK_A2L,SAMTEC_FTSH10501FDVK_A2M)
P6 = CONN_HEADER_2X2_P: User Part Number: #PN; alternate symbols: (GRADCONN_BB02HJ041KB1603000_A2C,GRADCONN_BB02HJ041KB1603000_A2A)
P8 = CONN_IDC_TC2050-IDC-NL: User Part Number: #PN; alternate symbols: (TAGCONNECT_TC2050IDCNL_A2L,TAGCONNECT_TC2050IDCNL_A2M)
PCB1 = PCB_V2: User Part Number: #PN
R1-R3 R5-R9 R14 R15 R20 R21 R23 R25 R27-R34 R39 R55-R63 R65 R87 R96-R100 R105 R106 R108 R111 R114 R117-R119 R131-R133 R135 R136 R138 R151 R152 R154 = RESISTOR: User Part Number: #PN
R11 R17 R18 R94 R95 R101-R104 R109 R110 R112 R113 R115 R116 R120 R121 R126-R130 R134 R137 R153 R155 R156 = RESISTOR: alternate symbols: (RESC1005X40A2L,RESC1005X40A2M)
R12 R46-R49 R51 R52 = RESISTOR: User Part Number: #PN; alternate symbols: (RESC1608X55A2L,RESC1608X55A2M)
R82-R84 R90-R93 = RESISTOR: User Part Number: #PN; alternate symbols: (RESC0603X35B2L,RESC0603X35B2M)
R107 = RESISTOR: User Part Number: #PN; alternate symbols: (RESC3246X70A2L,RESC3246X70A2M)
R122 = RESISTOR: User Part Number: #PN; alternate symbols: (RESC1005X50A2L,RESC1005X50A2M)
R123 = RESISTOR: User Part Number: #PN; alternate symbols: (RESC3216X75A2L,RESC3216X75A2M)
R125 = RESISTOR: User Part Number: #PN; alternate symbols: (RESC3225X75A2L,RESC3225X75A2M)
SW1-SW3 = SWITCH_TACT_V2: alternate symbols: (SW_1188E1K2V_A2L,SW_1188E1K2V_A2M)
U1 = IC_RF_CC1312R1F3_VQFN48: User Part Number: #PN; alternate symbols: (QFNFC50P700X700X100-49A2L,QFNFC50P700X700X100-49A2M)
U4 = IC_FLASH_MX25R8035F_USON8: User Part Number: #PN; alternate symbols: (SON50P300X200X60-9B2L,SON50P300X200X60-9B2M)
U5 = IC_PROC_TM4C1294NCPDT_TQFP128: alternate symbols: (QFP40P1600X1600X120-128L,QFP40P1600X1600X120-128M)
U6 = IC_REF_LM4040_SC70-5: alternate symbols: (SOT65P210X110-5L,SOT65P210X110-5M)
U7 U42 U46 = IC_PM_TPS79601_SON8: alternate symbols: (SON65P300X300X100-9AL,SON65P300X300X100-9AM)
U8-U10 = IC_XCVR_SN74AVC4T245_UQFN16_2: User Part Number: #PN; alternate symbols: (QFNFC40P180X260X55-16A2L,QFNFC40P180X260X55-16A2M)
U15 = IC_PROC_USB3300_QFN32: alternate symbols: (QFNWB50P500X500X100-33L,QFNWB50P500X500X100-33M,QFNWB50P500X500X100-33DL,QFNWB50P500X500X100-33DM)
U33 U38 = IC_SWITCH_TS3A24159_SON10: User Part Number: #PN; alternate symbols: (SON50P300X300X100-11A2L,SON50P300X300X100-11A2M)
U34 = IC_LOGIC_SN74LVC2G74_VSSOP8: alternate symbols: (SOP50P310X90-8L,SOP50P310X90-8M)
U35 = IC_ADC_ADS127L01_QFP32_0: User Part Number: #PN; alternate symbols: (QFP50P700X700X120-32A2L,QFP50P700X700X120-32A2M)
U36 = IC_OPAMP_INA118U_SO8: User Part Number: #PN; alternate symbols: (SOIC127P600X175-8A2L,SOIC127P600X175-8A2M)
U37 = IC_OPAMP_THS4551_QFN10: User Part Number: #PN; alternate symbols: (QFNFCP50P200X200X80-10A2L,QFNFCP50P200X200X80-10A2M)
U39 = IC_SWITCH_TS3A4751_QFN14: User Part Number: #PN; alternate symbols: (QFNFC40P200X200X40-14A2L,QFNFC40P200X200X40-14A2M)
U40 = IC_REF_REF6025_VSSOP8: User Part Number: #PN; alternate symbols: (SOP65P490X110-8A2L,SOP65P490X110-8A2M)
U41 = IC_OPAMP_OPA320_SOT23-5: User Part Number: #PN; alternate symbols: (SOT95P280X145-5A2L,SOT95P280X145-5A2M)
U43 = IC_PM_LP5907-1_8_SOT23-5: User Part Number: #PN; alternate symbols: (SOT95P280X145-5A2L,SOT95P280X145-5A2M)
U44 = IC_PM_TPS73101_SOT23-5: User Part Number: #PN; alternate symbols: (SOT95P280X145-5A2L,SOT95P280X145-5A2M)
U45 = IC_OPAMP_OPA314_SC70-5: User Part Number: #PN; alternate symbols: (SOT65P210X110-5A2L,SOT65P210X110-5A2M)
U47 = IC_PM_TPS259530_WSON8: alternate symbols: (SON50P200X200X80-9A2L,SON50P200X200X80-9A2M)
Y1 = CRYSTAL: User Part Number: #PN; alternate symbols: (XTAL_FC135_A2L,XTAL_FC135_A2M)
Y2 = XTAL_4PINS_1_3: User Part Number: #PN; alternate symbols: (OSCCC200X160X45-4A2L,OSCCC200X160X45-4A2M)
Y3 = XTAL_4: alternate symbols: (OSCCC250X320X100-4BL,OSCCC250X320X100-4BM)
Y4 = XTAL_4: alternate symbols: (OSCCC250X320X70-4AL,OSCCC250X320X70-4AM)
Y6 = XTAL_GEN_EN_V1: User Part Number: #PN; alternate symbols: (OSCSC254P320X500X130-4A2L,OSCSC254P320X500X130-4A2M)
Y7 = XTAL_GEN_V2: User Part Number: #PN; alternate symbols: (OSC_TG2016SMN_A2L,OSC_TG2016SMN_A2M)
Z60 = INDUCTOR_4: User Part Number: #PN
Z62 = INDUCTOR_4: alternate symbols: (IND_LQW15AL,IND_LQW15AM)

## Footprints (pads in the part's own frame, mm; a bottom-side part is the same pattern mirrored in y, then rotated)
ANTENNA_DN024N
  rect 2x1 smd: 1(0,0)
CAPC0603X35B2N
  custom 0.087x0.087 smd: 1(0,0) 2(0.56,0)
CAPC1005X60A2N
  custom 0.16x0.16 smd: 1(0,0) 2(0.9,0)
CAPC1005X60B2N
  custom 0.125x0.125 smd: 1(0,0) 2(0.924,0)
CAPC1608X90A2N
  custom 0.237x0.237 smd: 1(0,0) 2(1.6,0)
CAPC1608X100A2N
  custom 0.237x0.237 smd: 1(0,0) 2(1.6,0)
CAPC2012X150A2N
  custom 0.287x0.287 smd: 1(0,0) 2(1.8,0)
CAPMP7343X430A2N
  custom 0.588x0.588 smd: 1(0,0) 2(6.2,0)
FID127X142
  round 1.27 smd: 1(0,0)
FIL_BLM18HE152SN1DN
  custom 0.188x0.188 smd: 1(0,0) 2(1.4,0)
FIL_BLM18HE152SN1DN#2
  custom 0.237x0.237 smd: 1(0,0) 2(1.6,0)
FILC2012X110A2N
  custom 0.287x0.287 smd: 1(0,0) 2(1.8,0)
GRADCONN_BB02HC031KB1603000_A2B
  round 1.65 hole 1.05: 1(0,0) 2(2.54,0) 3(5.08,0)
GRADCONN_BB02HJ041KB1603000_A2B
  round 1.65 hole 1.05: 1(0,0) 2(0,2.54) 3(2.54,0) 4(2.54,2.54)
GRADCONN_BB02HJ221KB160300_A2B
  round 1.65 hole 1.05: 1(0,0) 2(0,2.54) 3(2.54,0) 4(2.54,2.54) 5(5.08,0) 6(5.08,2.54) 7(7.62,0) 8(7.62,2.54) 9(10.16,0) 10(10.16,2.54) 11(12.7,0) 12(12.7,2.54) 13(15.24,0) 14(15.24,2.54) 15(17.78,0) 16(17.78,2.54) 17(20.32,0) 18(20.32,2.54) 19(22.86,0) 20(22.86,2.54) 21(25.4,0) 22(25.4,2.54)
HUSTSAN_SMA10V21TGGAN
  round 1.8 smd: 1(0,0)
  custom 0.5x0.5 smd: 2(-2.8,-2.8) 3(2.8,-2.8) 4(2.8,2.8) 5(-2.8,2.8)
IND_LQW15AN
  custom 0.15x0.15 smd: 1(0,0) 2(0.98,0)
INDC1005X60B2N
  custom 0.125x0.125 smd: 1(0,0) 2(0.924,0)
INDC1005X60D2N
  custom 0.125x0.125 smd: 1(0,0) 2(0.924,0)
INDC2012X150A2N
  custom 0.287x0.287 smd: 1(0,0) 2(1.8,0)
LEDC1707X65N
  custom 0.188x0.188 smd: 1(0,0) 2(1.501,0)
LEDC1708X67N
  custom 0.188x0.188 smd: 1(0,0) 2(1.501,0)
MOLEX_1051640001_B2N
  custom 0.362x0.362 smd: (-1.162,0.35) (3.762,0.35)
  custom 0.35x0.35 smd: (0.362,2.65) (2.238,2.65)
  custom 0.113x0.113 smd: 1(0,0) 2(0.65,0) 3(1.3,0) 4(1.95,0) 5(2.6,0)
  oval 1.4x2.1 hole 0.6x1.3: M1(-2.65,2.65) M2(5.25,2.65)
MTG110_170
  round 1.699 hole 1.1: 1(0,0)
MTG320_380
  round 3.8 hole 3.2: 1(0,0)
OSC_TG2016SMN_A2N
  custom 0.15x0.15 smd: 1(0,0) 2(1.65,0) 3(1.65,1.13) 4(0,1.13)
OSCCC200X160X45-4A2N
  custom 0.2x0.2 smd: 1(0,0) 2(1.4,0) 3(1.4,1.1) 4(0,1.1)
OSCCC250X320X70-4AN
  custom 0.287x0.287 smd: 1(0,0) 2(2.5,0) 3(2.5,2) 4(0,2)
OSCCC250X320X100-4BN
  custom 0.299x0.299 smd: 1(0,0) 2(2.2,0) 3(2.2,1.699) 4(0,1.699)
OSCSC254P320X500X130-4A2N
  custom 0.3x0.3 smd: 1(0,0) 2(2.54,0) 3(2.54,2.2) 4(0,2.2)
QFN50P150X150X60-8N
  custom 0.075x0.075 smd: 1(0,0) 2(0.5,0) 3(1,0) 4(1.25,0.75) 5(1,1.5) 6(0.5,1.5) 7(0,1.5) 8(-0.25,0.75)
QFNFC40P180X260X55-16A2N
  custom 0.05x0.05 smd: 1(0,0) 2(0.4,-0.125) 3(0.8,-0.125) 4(1.2,-0.125) 5(1.825,0.09) 6(1.825,0.49) 7(1.825,0.89) 8(1.825,1.29) 9(1.2,1.505) 10(0.8,1.505) 11(0.4,1.505) 12(0,1.505) 13(-0.625,1.29) 14(-0.625,0.89) 15(-0.625,0.49) 16(-0.625,0.09)
QFNFC40P200X200X40-14A2N
  custom 0.05x0.05 smd: 1(0,0) 2(0.4,0) 3(0.8,0) 4(1.2,0) 5(1.6,0) 6(1.75,0.75) 7(1.75,1.15) 8(1.6,1.9) 9(1.2,1.9) 10(0.8,1.9) 11(0.4,1.9) 12(0,1.9) 13(-0.15,1.15) 14(-0.15,0.75)
QFNFC50P700X700X100-49A2N
  custom 0.075x0.075 smd: 1(0,0) 2(0.5,0) 3(1,0) 4(1.5,0) 5(2,0) 6(2.5,0) 7(3,0) 8(3.5,0) 9(4,0) 10(4.5,0) 11(5,0) 12(5.5,0) 13(6.2,0.7) 14(6.2,1.2) 15(6.2,1.7) 16(6.2,2.2) 17(6.2,2.7) 18(6.2,3.2) 19(6.2,3.7) 20(6.2,4.2) 21(6.2,4.7) 22(6.2,5.2) 23(6.2,5.7) 24(6.2,6.2) 25(5.5,6.9) 26(5,6.9) 27(4.5,6.9) 28(4,6.9) 29(3.5,6.9) 30(3,6.9) 31(2.5,6.9) 32(2,6.9) 33(1.5,6.9) 34(1,6.9) 35(0.5,6.9) 36(0,6.9) 37(-0.7,6.2) 38(-0.7,5.7) 39(-0.7,5.2) 40(-0.7,4.7) 41(-0.7,4.2) 42(-0.7,3.7) 43(-0.7,3.2) 44(-0.7,2.7) 45(-0.7,2.2) 46(-0.7,1.7) 47(-0.7,1.2) 48(-0.7,0.7)
  rect 5.25x5.25 smd: 49(2.75,3.45)
QFNFCP50P200X200X80-10A2N
  custom 0.075x0.075 smd: 1(0,0) 2(0.5,0) 3(1,0) 4(1.5,0) 5(1.67,0.885) 6(1.5,1.77) 7(1,1.77) 8(0.5,1.77) 9(0,1.77) 10(-0.1,0.885)
QFNWB50P500X500X100-33N
  oval 0.3x0.851 smd: 1(0,0) 2(0.5,0) 3(1,0) 4(1.5,0) 5(2,0) 6(2.5,0) 7(3,0) 8(3.5,0) 17(3.5,4.9) 18(3,4.9) 19(2.5,4.9) 20(2,4.9) 21(1.5,4.9) 22(1,4.9) 23(0.5,4.9) 24(0,4.9)
  oval 0.851x0.3 smd: 9(4.2,0.7) 10(4.2,1.2) 11(4.2,1.7) 12(4.2,2.2) 13(4.2,2.7) 14(4.2,3.2) 15(4.2,3.7) 16(4.2,4.2) 25(-0.7,4.2) 26(-0.7,3.7) 27(-0.7,3.2) 28(-0.7,2.7) 29(-0.7,2.2) 30(-0.7,1.7) 31(-0.7,1.2) 32(-0.7,0.7)
  rect 3.25x3.25 smd: 33(1.75,2.45)
QFP40P1600X1600X120-128N
  oval 0.201x1.501 smd: 1(0,0) 2(0.399,0) 3(0.8,0) 4(1.199,0) 5(1.6,0) 6(1.999,0) 7(2.4,0) 8(2.799,0) 9(3.2,0) 10(3.599,0) 11(4,0) 12(4.399,0) 13(4.801,0) 14(5.199,0) 15(5.601,0) 16(6,0) 17(6.401,0) 18(6.8,0) 19(7.201,0) 20(7.6,0) 21(8.001,0) 22(8.4,0) 23(8.801,0) 24(9.2,0) 25(9.601,0) 26(10,0) 27(10.399,0) 28(10.8,0) 29(11.199,0) 30(11.6,0) 31(11.999,0) 32(12.4,0) 65(12.4,15.4) 66(11.999,15.4) 67(11.6,15.4) 68(11.199,15.4) 69(10.8,15.4) 70(10.399,15.4) 71(10,15.4) 72(9.601,15.4) 73(9.2,15.4) 74(8.801,15.4) 75(8.4,15.4) 76(8.001,15.4) 77(7.6,15.4) 78(7.201,15.4) 79(6.8,15.4) 80(6.401,15.4) 81(6,15.4) 82(5.601,15.4) 83(5.199,15.4) 84(4.801,15.4) 85(4.399,15.4) 86(4,15.4) 87(3.599,15.4) 88(3.2,15.4) 89(2.799,15.4) 90(2.4,15.4) 91(1.999,15.4) 92(1.6,15.4) 93(1.199,15.4) 94(0.8,15.4) 95(0.399,15.4) 96(0,15.4)
  oval 1.501x0.201 smd: 33(13.899,1.501) 34(13.899,1.9) 35(13.899,2.301) 36(13.899,2.7) 37(13.899,3.099) 38(13.899,3.5) 39(13.899,3.899) 40(13.899,4.3) 41(13.899,4.699) 42(13.899,5.1) 43(13.899,5.499) 44(13.899,5.9) 45(13.899,6.299) 46(13.899,6.7) 47(13.899,7.099) 48(13.899,7.501) 49(13.899,7.899) 50(13.899,8.301) 51(13.899,8.7) 52(13.899,9.101) 53(13.899,9.5) 54(13.899,9.901) 55(13.899,10.3) 56(13.899,10.701) 57(13.899,11.1) 58(13.899,11.501) 59(13.899,11.9) 60(13.899,12.301) 61(13.899,12.7) 62(13.899,13.099) 63(13.899,13.5) 64(13.899,13.899) 97(-1.501,13.899) 98(-1.501,13.5) 99(-1.501,13.099) 100(-1.501,12.7) 101(-1.501,12.301) 102(-1.501,11.9) 103(-1.501,11.501) 104(-1.501,11.1) 105(-1.501,10.701) 106(-1.501,10.3) 107(-1.501,9.901) 108(-1.501,9.5) 109(-1.501,9.101) 110(-1.501,8.7) 111(-1.501,8.301) 112(-1.501,7.899) 113(-1.501,7.501) 114(-1.501,7.099) 115(-1.501,6.7) 116(-1.501,6.299) 117(-1.501,5.9) 118(-1.501,5.499) 119(-1.501,5.1) 120(-1.501,4.699) 121(-1.501,4.3) 122(-1.501,3.899) 123(-1.501,3.5) 124(-1.501,3.099) 125(-1.501,2.7) 126(-1.501,2.301) 127(-1.501,1.9) 128(-1.501,1.501)
QFP50P700X700X120-32A2N
  custom 0.075x0.075 smd: 1(0,0) 2(0.5,0) 3(1,0) 4(1.5,0) 5(2,0) 6(2.5,0) 7(3,0) 8(3.5,0) 9(4.95,1.45) 10(4.95,1.95) 11(4.95,2.45) 12(4.95,2.95) 13(4.95,3.45) 14(4.95,3.95) 15(4.95,4.45) 16(4.95,4.95) 17(3.5,6.4) 18(3,6.4) 19(2.5,6.4) 20(2,6.4) 21(1.5,6.4) 22(1,6.4) 23(0.5,6.4) 24(0,6.4) 25(-1.45,4.95) 26(-1.45,4.45) 27(-1.45,3.95) 28(-1.45,3.45) 29(-1.45,2.95) 30(-1.45,2.45) 31(-1.45,1.95) 32(-1.45,1.45)
RESC0603X35B2N
  custom 0.087x0.087 smd: 1(0,0) 2(0.56,0)
RESC1005X40A2N
  custom 0.16x0.16 smd: 1(0,0) 2(0.9,0)
RESC1005X40B2N
  custom 0.125x0.125 smd: 1(0,0) 2(0.924,0)
RESC1005X50A2N
  custom 0.16x0.16 smd: 1(0,0) 2(0.9,0)
RESC1608X55A2N
  custom 0.237x0.237 smd: 1(0,0) 2(1.6,0)
RESC3216X75A2N
  custom 0.287x0.287 smd: 1(0,0) 2(3,0)
RESC3225X75A2N
  custom 0.287x0.287 smd: 1(0,0) 2(3,0)
RESC3246X70A2N
  custom 0.287x0.287 smd: 1(0,0) 2(2.9,0)
SAMTEC_FTSH10501FDVK_A2N
  custom 0.188x0.188 smd: 1(0,0) 2(0,3.85) 3(1.27,0) 4(1.27,3.85) 5(2.54,0) 6(2.54,3.85) 7(3.81,0) 8(3.81,3.85) 9(5.08,0) 10(5.08,3.85)
SAMTEC_SSQ11023LD_A2B
  round 1.65 hole 1.05: 1(0,0) 2(2.54,0) 3(0,2.54) 4(2.54,2.54) 5(0,5.08) 6(2.54,5.08) 7(0,7.62) 8(2.54,7.62) 9(0,10.16) 10(2.54,10.16) 11(0,12.7) 12(2.54,12.7) 13(0,15.24) 14(2.54,15.24) 15(0,17.78) 16(2.54,17.78) 17(0,20.32) 18(2.54,20.32) 19(0,22.86) 20(2.54,22.86)
SOD3716X135N
  oval 1.15x0.8 smd: 1(0,0) 2(3.5,0)
SODFL2512X80A2N
  custom 0.113x0.113 smd: 1(0,0) 2(2.28,0)
SOIC127P600X175-8A2N
  custom 0.15x0.15 smd: 1(0,0) 2(1.27,0) 3(2.54,0) 4(3.81,0) 5(3.81,4.95) 6(2.54,4.95) 7(1.27,4.95) 8(0,4.95)
SON50P100X145X60-6B2N
  custom 0.075x0.075 smd: 1(0,0) 2(0.5,0) 3(1,0) 4(1,0.59) 5(0.5,0.59) 6(0,0.59)
SON50P200X200X80-9A2N
  custom 0.075x0.075 smd: 1(0,0) 2(0.5,0) 3(1,0) 4(1.5,0) 5(1.5,2.1) 6(1,2.1) 7(0.5,2.1) 8(0,2.1)
  rect 1.7x0.9 smd: 9(0.75,1.05)
SON50P300X200X60-9B2N
  custom 0.075x0.075 smd: 1(0,0) 2(0.5,0) 3(1,0) 4(1.5,0) 5(1.5,2.4) 6(1,2.4) 7(0.5,2.4) 8(0,2.4)
  rect 1.7x0.3 smd: 9(0.75,1.2)
SON50P300X300X100-11A2N
  custom 0.062x0.062 smd: 1(0,0) 2(0.5,0) 3(1,0) 4(1.5,0) 5(2,0) 6(2,2.94) 7(1.5,2.94) 8(1,2.94) 9(0.5,2.94) 10(0,2.94)
  custom 0.412x0.412 smd: 11(1,1.47)
SON65P300X300X100-9AN
  custom 0.075x0.075 smd: 1(0,0) 2(0.65,0) 3(1.3,0) 4(1.95,0) 5(1.95,3) 6(1.3,3) 7(0.65,3) 8(0,3)
  rect 2.5x1.65 smd: 9(0.975,1.5)
SOP50P310X90-8N
  oval 0.3x0.851 smd: 1(0,0) 2(0.5,0) 3(1,0) 4(1.5,0) 5(1.5,3.1) 6(1,3.1) 7(0.5,3.1) 8(0,3.1)
SOP65P490X110-8A2N
  custom 0.113x0.113 smd: 1(0,0) 2(0.65,0) 3(1.3,0) 4(1.95,0) 5(1.95,4.3) 6(1.3,4.3) 7(0.65,4.3) 8(0,4.3)
SOT65P210X110-5A2N
  custom 0.1x0.1 smd: 1(0,0) 2(0.65,0) 3(1.3,0) 4(1.3,1.92) 5(0,1.92)
SOT65P210X110-5N
  oval 0.399x0.899 smd: 1(0,0) 2(0.65,0) 3(1.3,0) 4(1.3,2.2) 5(0,2.2)
SOT95P280X145-5A2N
  custom 0.15x0.15 smd: 1(0,0) 2(0.95,0) 3(1.9,0) 4(1.9,2.29) 5(0,2.29)
SW_1188E1K2V_A2N
  round 0.099 hole 0.899 unplated: (2.229,0.6) (4.529,0.6)
  custom 0.25x0.25 smd: 1(0,0) 2(6.75,0)
  custom 0.225x0.225 smd: 3(1.275,1.8) 4(5.475,1.8)
TAGCONNECT_TC2050IDCNL_A2N
  round 0.1 hole 1 unplated: (-1.27,0.635) (6.35,-0.38) (6.35,1.65)
  round 0.8 smd: 1(0,0) 2(1.27,0) 3(2.54,0) 4(3.81,0) 5(5.08,0) 6(5.08,1.27) 7(3.81,1.27) 8(2.54,1.27) 9(1.27,1.27) 10(0,1.27)
unnamed#2
  round 0.099 hole 3.2 unplated: (0,0) (15,0)
XTAL_FC135_A2N
  custom 0.25x0.25 smd: 1(0,0) 2(2.5,0)

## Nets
5V0: C48.1 C110.1 C111.2 C112.1 C151.1 C152.1 C157.1 C160.1 C161.1 C164.1 C165.1 C166.1 C171.1 C175.1 FL2.1 P4.19 R82.2 R92.2 R153.2 U7.1 U7.2 U7.8 U42.1 U42.2 U42.8 U43.1 U43.3 U44.1 U44.3 U46.1 U46.2 U46.8
5V0_BP: J1.2 P2.1 P4.20
GND: C1.2 C2.2 C3.2 C4.2 C6.2 C7.2 C8.2 C9.2 C11.2 C12.2 C14.2 C15.2 C16.2 C17.2 C18.2 C19.2 C20.2 C22.2 C23.2 C24.2 C30.2 C31.2 C33.2 C34.2 C35.2 C38.2 C39.2 C40.2 C41.2 C42.2 C43.2 C44.2 C45.2 C46.2 C48.2 C49.2 C50.2 C51.2 C52.2 C53.2 C70.2 C71.2 C72.2 C73.2 C74.2 C75.2 C78.2 C79.2 C80.2 C83.2 C84.2 C85.1 C86.1 C87.2 C88.1 C89.1 C106.2 C107.2 C108.2 C109.2 C110.2 C111.1 C112.2 C113.2 C114.2 C115.2 C116.2 C117.2 C118.2 C119.2 C120.2 C121.2 C122.2 C124.1 C125.1 C126.1 C127.2 C128.2 C133.2 C134.2 C136.2 C137.2 C138.2 C139.2 C140.2 C141.2 C142.2 C143.2 C144.2 C145.2 C147.2 C149.2 C151.2 C152.2 C154.2 C155.2 C156.2 C157.2 C158.2 C159.2 C160.2 C161.2 C162.2 C163.2 C164.2 C165.2 C166.2 C167.2 C168.2 C170.1 C171.2 C173.2 C174.2 C175.2 CR1.1(C) CR2.1(C) CR4.1(C) CR5.1(C) CR6.3 CR7.4 CR8.4 CR14.2 CR15.2 J1.4 J2.2 J6.5 J7.2 J7.3 J7.4 J7.5 MH3.1 MH4.1 MH5.1 P1.2 P1.3 P2.2 P2.3 P4.21 P4.22 P5.3 P5.5 P5.9 P7.3 P7.5 P7.9 P8.3 P8.5 P8.9 R21.2 R28.1 R29.2 R30.2 R32.1 R34.1 R61.1 R62.1 R63.1 R65.1 R84.1 R90.1 R91.1 R93.2 R97.2 R105.1 R106.1 R115.2 R116.1 R117.1 R118.1 R122.1 R123.1 R125.1 R126.1 R127.2 R128.2 R129.2 R130.2 R133.1 R135.1 R136.1 R152.1 R155.1 R156.1 SW1.1 SW1.2 SW1.3 SW2.1 SW2.2 SW2.4 SW3.1 SW3.2 SW3.4 U1.49 U4.4 U4.9 U5.10 U5.17 U5.48 U5.55 U5.58 U5.64 U5.66 U5.80 U5.114 U6.1 U7.6 U7.9 U8.1 U8.5 U8.7 U8.10 U8.11 U8.16 U9.1 U9.5 U9.10 U9.11 U9.13 U9.16 U10.7 U10.9 U10.10 U10.11 U10.12 U10.16 U15.1 U15.2 U15.33 U33.6 U33.11 U34.4 U35.5 U35.10 U35.13 U35.14 U35.18 U35.26 U35.30 U35.31 U36.4(V-) U37.5(VS-) U38.6 U38.7 U38.8 U38.9 U38.10 U38.11 U39.7 U39.10 U39.11 U39.12 U40.7 U40.8 U41.2(V-) U42.6 U42.9 U43.2 U44.2 U45.2(V-) U46.6 U46.9 U47.8 U47.9 Y2.2 Y2.4(GND#4) Y3.2 Y3.4 Y4.2 Y4.4 Y6.2 Y7.2 Z61.2 Z62.2
VBUS_DET: R92.1 R93.1 U5.12
VDDC: C43.1 C44.1 C45.1 U5.87(VDDC#87) U5.115
VDDR: C18.1 C19.1 C20.1 L10.2 U1.45 U1.48
VDDS: C12.1 C14.1 C15.1 C16.1 C17.1 FL1.1 R1.2 U1.13 U1.22 U1.34 U1.44
BP_RESET: J2.11 R52.1
DCDC_SW: L10.1 U1.33
DIO1: J1.20 U1.6
DIO4_SCL: J1.17 R2.1 U1.9
DIO5_SDA: J1.19 R3.1 U1.10
DIO6_RLED: J2.3 P6.2 U1.11
DIO7_GLED: J2.1 P6.4 U1.12
DIO8_MISO: J2.14 U1.14 U4.2
DIO9_MOSI: J2.12 U1.15(DIO_9) U4.5
DIO10_SCLK: J1.13 U1.16 U4.6
DIO11_CS: J2.6 U1.17
DIO12: J2.4 U1.18
DIO13_BTN1: J2.16 R56.2 U1.19
DIO14_BTN2: J2.18 R55.2 U1.20
DIO15: J2.20 U1.21
DIO16_TDO: CR8.5 P4.6 P5.6 R48.2 U1.26
DIO17_TDI: CR8.3 P4.4 P5.8 R49.2 U1.27
DIO19_CTS: J2.7 U1.29
DIO20_FLASH_CS: J2.5 R11.2 U1.30 U4.1
DIO21: J1.15 U1.31
DIO22: J1.9 U1.32
DIO23_ANALOG: J1.3 U1.36
DIO24_ANALOG: J1.11 U1.37
DIO25_ANALOG: J1.6 U1.38
DIO26_ANALOG: J1.8 U1.39
DIO27_ANALOG: J1.10 U1.40
DIO28_ANALOG: J1.12 U1.41
DIO29_ANALOG: J1.14 U1.42
DIO30/TCXO_VCC: R8.2 R9.1 U1.43
DIO30_ANALOG: J1.16 R9.2
ET_1V8: C128.1 C158.1 C159.1 U35.1 U43.5(OUT)
ET_3V3: C126.2 C141.1 C142.1 C153.1 C154.1 C155.1 C156.1 FL5.1 FL6.2 R132.2 U37.3 U37.10 U40.1(VIN) U40.2 U41.5 U42.3 U42.4(OUT#4)
ET_5V0: C125.2 C167.1 C168.1 FL3.1 U36.7
ET_AVDD: C119.1 C120.1 C121.1 C122.1 FL6.1 R98.1 U35.6 U35.32
ET_BYPASS: U5.78 U33.4 U33.8
ET_CAL0: R129.1 U5.74 U39.13
ET_CAL1: R128.1 U5.73 U39.5
ET_CAL2: R127.1 U5.23 U39.6
ET_CALIBRATE: U5.77 U38.4
ET_DVDD: C116.1 C117.1 FL4.1 FL5.2 R96.1 R114.1 R119.1 U35.27 Y6.1
ET_FB: C169.2 R138.1 U45.3 U45.4
ET_PM2: R96.2 U5.76 U35.17(START)
ET_PN3: R114.2 U5.110 U35.28
ET_SSICLK: U5.120 U35.22
ET_SSIDAT0: U5.123 U35.21
ET_SSIDAT1: U5.124 U35.20
ET_SSIFSS: U5.121 U35.19
ET_VDD: C172.1 C173.1 C174.1 CR14.1(CATHODE) P10.1 R151.2 U46.3 U46.4(OUT#4)
ET_VREF: C127.1 C146.1 R121.1 U35.9 U40.5 U40.6
IRSTN: P8.10 R20.2
ITCK: P8.4 U5.100
ITDI: P8.8 U5.98
ITDO: P8.6 U5.97
ITMS: P8.2 U5.99
LP_RESET: J2.10 R51.1
LS_VDD: C70.1 C72.1 C74.1 CR7.8(VCC) P7.1 P10.2 U8.2(VCCB) U9.2(VCCB) U10.2(VCCB) U33.3 U33.9
SW_VDD: C114.1 C139.1 C140.1 C162.1 C163.1 C170.2 R134.2 U33.1(VCC) U38.1(VCC) U39.14(VCC) U44.5(OUT) U45.5
TARGET_VDD: P4.17 U38.5
TCXO_OUTPUT: C25.2 R7.1
USB1V8: C83.1 C84.1 C85.2 U15.15 U15.26
USB_VBUS: C106.1 CR6.6(VCC) J6.1(VCC) R154.1 U47.3 U47.4
USBA1V8: C86.2 C87.1 U15.29
USBCLK: U5.92 U15.14
USBD0: U5.81 U15.24
USBD1: U5.82 U15.23
USBD2: U5.83 U15.22
USBD3: U5.84 U15.21
USBD4: U5.85 U15.20
USBD5: U5.86 U15.19
USBD6: U5.106 U15.18
USBD7: U5.105 U15.17
USBDIR: U5.104 U15.12
USBDM: CR6.5 J6.2 U15.8
USBDP: CR6.4 J6.3 U15.7
USBNXT: U5.103 U15.11
USBSTP: U5.91 U15.13
VCM: R100.1 R109.2 R111.2 R131.1 U41.1
WMCU_RESET: C52.1 CR8.2 P4.12 P5.10 R1.1 R51.2 R52.2 U1.35
WMCU_RXD: J1.5 P4.16 U1.7
WMCU_SWO: J2.9 P4.2 U1.28
WMCU_TCK: CR8.6 P4.8 P5.4 R47.2 U1.25
WMCU_TMS: CR8.7 P4.10 P5.2 R46.2 U1.24
WMCU_TXD: J1.7 P4.14 U1.8
WMCU_VDD: CR8.8(VCC) FL1.2 J1.1 P1.1 P4.18 P5.1 P10.3 R2.2 R3.2 R11.1 R12.2 R59.2 R60.2
XDS_RESET: R58.1 U5.40 U10.1 U10.6
XDS_RESET_LS: CR7.2 P4.11 P7.10 R57.2 U10.15
XDS_RX: U5.33 U8.8
XDS_RX_LS: P4.13 R61.2 U8.13
XDS_SWO: U5.25 U8.9
XDS_SWO_LS: P4.1 R62.2 U8.12
XDS_TCK: U5.35 U9.6
XDS_TCK_LS: CR7.6 P4.7 P7.4 U9.15
XDS_TDI: U5.38 U9.7
XDS_TDI_LS: CR7.3 P4.3 P7.8 U9.14
XDS_TDO: U5.37 U9.9
XDS_TDO_LS: CR7.5 P4.5 P7.6 R63.2 U9.12
XDS_TMS: U5.36 U10.8
XDS_TMS_DIR: U5.24 U10.5
XDS_TMS_LS: CR7.7 P4.9 P7.2 R65.2 U10.13
XDS_TX: U5.34 U8.6
XDS_TX_LS: P4.15 U8.15
XDS_VDD: C2.1 C3.1 C4.1 C6.1 C7.1 C38.1 C39.1 C40.1 C42.1 C47.1 C49.1 C71.1 C73.1 C75.1 C78.1 C79.1 C80.1 C113.1 P8.1 R17.2 R18.2 R27.1 R31.2 R33.2 R39.1 R58.2 R83.1 U5.7 U5.8 U5.16 U5.26 U5.28 U5.39 U5.47 U5.51 U5.52 U5.69 U5.79 U5.90 U5.101 U5.113 U5.122 U7.3 U7.4(OUT#4) U8.3 U8.4 U9.3 U9.4 U10.3 U10.4 U15.6 U15.16 U15.25 U15.30 U15.31
N949215: R17.1 R20.1 R21.1 U5.70
N949243: R30.1 U5.60
N949263: C47.2 R33.1 R34.2 U7.5
N949375: R28.2 U5.59
N949687: C1.1 U5.89 Y3.3
N949699: C9.1 U5.88 Y3.1
N950083: C8.1 C50.1 R18.1 U5.9 U6.3
N951001: R39.2 U5.63
N951013: R29.1 U5.61
N951017: R27.2 U5.62
N952443: C46.1 R31.1 U5.68
N1004371: R23.2 U5.3
N1004534: R25.2 U5.4
N1014101: C41.1 U1.4 Y1.1
N1014113: C51.1 U1.5 Y1.2
N1017630: C30.1 R12.1 U4.8(VCC)
N1018954: C22.1 R5.2 Y2.1
N1031635: CR6.1 J6.M1 J6.M2 R32.2
N1105722: CR1.2 R15.1
N1105771: CR2.2 R14.1
N1105824: P6.1 R14.2
N1106228: P6.3 R15.2
N1176548: J2.15 R47.1
N1176568: J2.17 R48.1
N1177007: J2.19 R49.1
N1288065: R55.1 SW2.3
N1288098: R56.1 SW1.4
N1384129: R57.1 SW3.3
N1409884: R59.1 U4.3
N1409917: R60.1 U4.7
N1553941: R83.2 U15.5
N1579665: R84.2 U15.32
N1580179: C88.2 R87.2 U15.28 Y4.1
N1580186: C89.2 R87.1 U15.27(XO) Y4.3
N1644260: R90.2 U5.95
N1644363: R91.2 U5.96
N2070550: C53.1 U1.23
N2071733: C11.1 L11.1 L12.2 U1.1
N2072219: C21.1 L12.1 L32.1 U1.2
N2074535: C31.1 L32.2 U1.3
N2075216: C21.2 C33.1 L11.2 L33.1
N2075665: C34.1 L33.2 L34.1
N2076038: C35.1 C36.1 C37.1 L34.2
N2078765: C37.2 J7.1
N2082297: Z60.2 Z61.1 Z62.1 Z63.1
N2239551: R5.1 R7.2 U1.47
N2239563: R6.1 U1.46
N2245591: A1.1 Z63.2
N2266542: C36.2 Z60.1
N3002303: C115.1 C118.1 FL4.2 U34.6 U34.7 U34.8(VCC) Y6.4(VCC)
N3002611: R99.2 R107.1 U33.2
N3002631: U34.1 Y6.3
N3002671: U34.2 U34.3
N3002679: R94.2 U34.5
N3002683: R94.1 U35.24
N3002707: R107.2 R108.2 U33.7 U38.3 U45.1
N3002889: C129.1 R95.2 R101.1 R102.2
N3002897: R95.1 R103.1 R104.2
N3003137: C123.1 C130.1 R102.1 U37.4
N3003145: C123.2 R103.2 U37.1
N3003349: R97.1 U35.29
N3003461: C124.2 C132.1 R99.1 U36.3
N3003521: R98.2 U35.8
N3003585: R137.1 U36.8
N3003709: R101.2 U36.6
N3003761: C131.1 R104.1 U35.3
N3003773: R105.2 U35.23
N3003833: C132.2 C134.1 R108.1 U36.2
N3003845: C133.1 R111.1 U37.7
N3003889: R100.2 R106.2 U36.5
N3003929: C130.2 C135.1 R110.1 U37.6
N3003937: C135.2 R112.2 U37.9
N3003989: C136.1 U35.2
N3004061: C129.2 R109.1 R110.2 R115.1 R120.2
N3004137: C131.2 R113.1 U35.4
N3004141: C137.1 U35.11
N3004269: R112.1 R113.2 R120.1
N3004289: C138.1 U35.25
N3004389: R116.2 U35.7
N3004561: R117.2 U35.16
N3004593: R118.2 U35.15
N3004681: R119.2 U35.12
N3004851: U38.2 U39.2 U39.4 U39.9
N3005293: C143.1 R123.2 U39.1
N3005369: R136.2 U40.3
N3005381: C147.1 R121.2 R126.2 U41.3
N3005457: C145.1 U40.4
N3005465: C146.2 R122.2
N3005509: C144.1 R125.2 U39.3
N3005629: R131.2 U41.4
N3005723: C149.1 R130.1 U39.8
N3011605: C153.2 R132.1 R133.2 U42.5
N3011753: C169.1 C172.2 R138.2 R151.1 R152.2 U46.5
N3012529: R134.1 R135.2 U44.4
N3025885: R137.2 U36.1
N3156339: FL3.2 R153.1
N3157182: C23.1 R6.2 Y2.3
N3167465: C108.1 C109.1 CR15.1(CATHODE) FL2.2 U47.5(OUT)
N3174121: CR6.2 J6.4
N3220034: J2.13 R46.1
N3261415: R154.2 R155.2 U47.2
N3263468: C107.1 U47.1
N3266724: R156.2 U47.7
N3270349: R82.1 U15.4
N3291381: C25.1 Y7.3
N3291400: C24.1 R8.1 Y7.4(VCC)
N10367920: CR5.2 R25.1
N10368080: CR4.2 R23.1

Pads without a net: CR7 1; CR8 1; FIDU1 1; FIDU2 1; FIDU3 1; FIDU4 1; FIDU5 1; FIDU6 1; J1 18; J2 8; MH1 1; MH2 1; P5 7; P7 7; P8 7; U5 1 2 5 6 11 13 14 15 18 19 20 21 22 27 29 30 31 32 41 42 43 44 45 46 49 50 53 54 56 57 65 67 71 72 75 93 94 102 107 108 109 111 112 116 117 118 119 125 126 127 128; U6 2 4 5; U7 7; U8 14; U9 8; U10 14; U15 3 9 10; U33 5 10; U37 2 8; U42 7; U43 4; U46 7; U47 6; Y7 1

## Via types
v1: diameter 0.4, hole 0.2, TOP to BOTTOM, 1369 vias
v2: diameter 0.5, hole 0.201, TOP to BOTTOM, 25 vias

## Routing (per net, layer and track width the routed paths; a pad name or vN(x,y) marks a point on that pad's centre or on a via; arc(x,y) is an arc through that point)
5V0: length 154.1
  TOP w0.15: U44.3 35.75,91.35 36.35,91.95 37.65,91.95 ; R82.2 9.47,112.06 8.81,112.73 6.88,112.73 6.75,112.6 v1(6.35,112.6)
  TOP w0.3: 26.75,108.5 U7.2 ; v1(31.1,98.8) 31.3,99 U42.8 ; U43.3 34.85,102.85 34.55,103.15 34.55,104.4 C164.1 ; v1(30.67,111.25) 30.7,111.25 30.75,111.2 ; R92.2 v1(11.45,84.2) ; U7.8 v1(27.1,104.7) ; 34.9,99 35.1,99.2 35.1,99.45 35.1,99.45 U42.2 U42.1 ; U46.8 v1(30.95,115.8) ; 31.45,112.15 U46.2
  TOP w0.5: C110.1 23.45,113.3 FL2.1
  TOP w0.6: 34.3,105.15 34.75,105.15 35.05,105.45 v1(35.05,105.45) ; 34.3,105.15 C157.1 ; 34.3,105.15 C164.1 34.4,104.75 U43.1 ; v1(38.3,97.4) 37.55,96.65 C165.1 ; FL2.1 23.6,112.4 C111.2 26.8,112.4 C112.1 27.65,111.35 ; C160.1 37.55,93.65 C161.1 37.65,92.5 U44.1 ; C160.1 37.55,93.75 ; C160.1 v1(38.65,93.7) v1(38.65,94.5) ; 27.75,108.5 27.75,109.7 v1(27.65,109.8) ; 27.75,108.5 U7.1 26.75,108.5 ; 27.75,108.5 C48.1 28.4,108.5 ; R153.2 37.85,96 C165.1 ; C171.1 C175.1 ; C175.1 30.75,111.95 U46.1 31.45,112.15 ; C175.1 30.6,110.5 29.9,109.8 v1(28.55,109.8) ; C165.1 C166.1 ; U42.1 36.05,99 C152.1 36.1,98.05 C151.1 v1(35.2,98) v1(34.55,98)
  TOP w1: v1(28.55,109.8) v1(27.65,109.8) 27.65,111.35
  L3 w0.15: v1(6.35,112.6) 6.35,113.8 7.45,114.9 19.91,114.9 20.81,115.8 25.37,115.8 26.07,115.1 26.07,113.7 27.67,112.1 27.67,109.82 v1(27.65,109.8)
  L3 w0.3: v1(30.67,111.25) 30.23,111.69 30.23,115.5 30.53,115.8 v1(30.95,115.8) ; v1(34.55,98) 31.18,98 31.11,97.93 31.1,97.94 v1(31.1,98.8) ; v1(27.1,104.7) 27.91,104.7
  L3 w0.6: v1(38.65,93.7) 38.63,93.7 ; 38.16,97.4 v1(38.3,97.4) ; v1(35.05,105.45) 34.49,105.45 33.74,104.7 27.91,104.7 ; v1(34.55,98) 34.6,97.95 ; v1(38.65,94.5) 38.63,94.5
  L3 w1: 29.91,97.93 29.53,97.93 24.4,92.8 15.15,92.8 v1(12.9,90.55) v1(12.9,89.7) ; 29.91,97.93 27.91,99.93 27.91,108.74 28.55,109.38 v1(28.55,109.8) v1(27.65,109.8) ; 29.91,97.93 34.7,97.93 34.71,97.93 34.71,97.93 37.63,97.93 38.63,96.93 38.63,93.7
  BOTTOM w0.3: 13.95,84.25 13.9,84.2 v1(11.45,84.2)
  BOTTOM w1: v1(12.9,90.55) v1(12.9,89.7) 12.9,88.8 13.95,87.75 P4.19
5V0_BP: length 54.5
  BOTTOM w1: P4.20 8.87,73.54 ; 8.87,73.54 3.65,68.32 3.65,36.67 4.9,35.42 P2.1 ; 8.87,73.54 J1.2
GND: length 302.9
  TOP w0.15: 7.21,38.82 P2.2 5.49,37.1 ; 12.27,82.02 P4.21 10.55,80.3 ; 52.07,69.54 J2.2 51.21,67.6 ; v1(34.55,43.55) 34.52,43.52 C41.2 33.85,44.16 33.9,44.21 C51.2 34.57,44.68 v1(34.6,44.65) ; 51.19,37.1 P1.2 52.91,38.82 ; 11.41,82.24 11.41,82.22 ; 8.01,65.06 J1.4 9.73,66.78 ; 3.75,95 2.05,95 ; 11.41,77.54 11.41,77.75 ; v1(31.27,105.6) 31.16,105.6 30.98,105.42 CR14.2 ; v1(18.75,29.35) 18.65,29.35 ; Y3.2 2.5,107.15 v1(2.8,106.85) ; 7.21,41.36 P2.3 5.49,39.64 ; 52.05,36.88 52.05,37.05 ; 10.55,77.76 P4.22 10.34,78.62 ; 51.19,39.64 P1.3 52.91,41.36 ; 51,68.46 51.2,68.46 ; 7.43,40.5 7.3,40.5 ; v1(11.7,111.22) CR6.3 ; 8.87,67 8.87,66.75 ; 52.07,67.38 52.07,67.55
  TOP w0.2: v1(33.11,91.55) 33.11,91.55 33.11,91.84 R127.2 32.45,92.5 U39.7 ; v1(26.1,106.5) 25.8,106.2 U7.6 25.8,104.9 26.2,104.5 R34.1 ; U39.11 33.95,94.6 34.15,94.4 v1(34.23,94.4) 34.03,94.2 U39.10 ; U39.12 v1(34.15,95)
  TOP w0.201: 11.1,109.1 11.6,109.6 U15.1 ; 11.1,109.1 v1(10.9,108.9) ; 11.1,109.1 U15.2
  TOP w0.3: U46.6 32.25,114.55 v1(31.9,114.2) ; C107.2 17.65,113.7 v1(18.15,113.2) 18.15,112.6 U47.8 17.25,112.5 v1(17,112.25) ; v1(29.15,107.65) 29.1,107.6 C48.2 28.75,107.25 28.75,107 v1(28.85,106.9) ; v1(27.5,58.9) 27.42,58.82 C17.2 ; v1(26.45,59.7) 26.32,59.57 C16.2 ; C106.2 12.7,112.62 12.7,113.95 J6.5 ; 54.65,76.97 55.92,78.25 56.45,78.25 ; v1(21.92,110.85) CR15.2 v1(23.8,110.85) ; R156.1 v1(19.15,114.4) ; C49.2 v1(23.75,106.85) ; v1(21.65,113.7) 21.75,113.6 C110.2 ; C108.2 20.9,113.47 v1(20.9,113.95) ; v1(20.15,113.95) C109.2 ; v1(21.62,106.9) C113.2 ; v1(24.7,114.8) C111.1
  TOP w0.6: MH5.1 2.95,80.3 ; MH5.1 2.95,82.65 ; MH5.1 1.5,81.6 ; MH5.1 4.2,81.6
  TOP w0.7: P2.3 5.27,40.5 ; P2.3 7.3,40.5 ; P2.3 6.35,39.42 ; P2.3 6.35,41.58 ; J1.4 9.95,65.92 ; J1.4 8.87,64.84 ; J1.4 7.8,65.92 ; J1.4 8.87,66.75 ; 51.2,68.46 J2.2 ; J2.2 53.15,68.46 ; J2.2 52.07,67.55 ; 11.41,79.86 P4.22 ; P4.22 11.38,78.65 10.2,78.65 ; P4.22 11.41,77.75 ; P4.22 12.49,78.62 ; 6.35,39.2 P2.2 ; P2.2 6.35,36.88 ; P2.2 5.27,37.96 ; P2.2 7.43,37.96 ; 11.41,80.08 P4.21 ; P4.21 12.49,81.16 ; P4.21 10.34,81.16 ; P4.21 11.41,82.22 ; P1.3 53.13,40.5 ; P1.3 50.97,40.5 ; P1.3 P1.2 ; P1.3 52.05,41.58 ; P1.2 50.76,37.96 ; P1.2 52.05,37.05 ; P1.2 53.13,37.96
  L2 w0.15: 4.07,118.32 MH3.1 0.83,115.08 ; 2.07,80.72 MH5.1 3.83,82.48 ; 6.35,39.04 6.35,38.85 ; 10.55,77.76 P4.22 12.27,79.48 ; 54.13,118.32 MH4.1 54.13,115.08 ; 9.73,66.78 J1.4 8.01,65.06 ; 52.94,69.32 J2.2 51.21,67.6 ; 8.87,64.84 8.87,65.05 ; 5.49,37.1 P2.2 7.21,38.82 ; 10.55,80.3 P4.21 12.27,82.02 ; 7.21,41.36 P2.3 5.49,39.64 ; 51.19,39.64 P1.3 52.91,41.36 ; 52.91,38.82 P1.2 51.19,37.1 ; 7.8,65.92 7.95,65.92 ; 11.41,80.08 11.41,80.3 ; 11.41,82.24 11.41,82.22 ; 12.49,78.62 12.3,78.62 ; 6.35,39.42 6.35,39.65
  L2 w0.3: 35.15,113.6 34.8,113.6 v1(32.2,111)
  L2 w0.7: P1.3 52.05,39.42 ; P1.3 50.97,40.5 ; P1.3 52.05,41.58 ; P1.3 53.13,40.5 ; P2.2 5.27,37.96 ; P2.2 6.35,38.85 ; P2.2 7.43,37.96 ; P2.2 6.35,36.88 ; MH5.1 1.85,81.6 ; MH5.1 2.95,82.7 ; MH5.1 4.1,81.6 ; MH5.1 2.95,80.5 ; P1.2 50.97,37.96 ; P1.2 52.05,36.88 ; P1.2 52.05,39.04 ; P1.2 53.13,37.96 ; 12.3,78.62 P4.22 ; P4.22 11.41,79.7 ; P4.22 11.41,77.54 ; P4.22 10.34,78.62 ; P2.3 6.35,41.58 ; P2.3 6.35,39.65 ; P2.3 5.27,40.5 ; P2.3 7.43,40.5 ; 11.41,82.22 P4.21 ; P4.21 10.34,81.16 ; P4.21 11.41,80.3 ; P4.21 12.49,81.16 ; J2.2 53.15,68.46 ; J2.2 51,68.46 ; J2.2 52.07,67.38 ; J2.2 52.07,69.54 ; 8.87,65.05 J1.4 ; J1.4 7.95,65.92 ; J1.4 9.95,65.92 ; J1.4 8.87,67
  L2 w1: v1(51.15,115.9) 51.95,116.7 MH4.1 55.75,114 v1(55.15,113.4) ; 5.3,116.7 MH3.1 v1(2.45,113.75)
  L3 w0.15: J2.2 53.15,68.46 ; J2.2 52.07,67.38 ; J2.2 51,68.46 ; J2.2 52.07,69.54 ; 10.34,78.62 P4.22 ; P4.22 11.41,77.54 ; P4.22 11.41,79.7 ; P4.22 12.49,78.62 ; 0.83,115.08 MH3.1 4.07,118.32 ; P1.2 53.13,37.96 ; P1.2 52.05,36.88 ; P1.2 50.97,37.96 ; P1.2 52.05,39.04 ; P4.21 12.49,81.16 ; P4.21 10.34,81.16 ; P4.21 11.41,82.24 ; P4.21 11.41,80.08 ; 50.97,40.5 P1.3 ; P1.3 52.05,39.42 ; P1.3 52.05,41.58 ; P1.3 53.13,40.5 ; 5.27,40.5 P2.3 ; P2.3 7.43,40.5 ; P2.3 6.35,39.42 ; P2.3 6.35,41.58 ; P2.2 7.43,37.96 ; P2.2 6.35,39.04 ; P2.2 5.27,37.96 ; P2.2 6.35,36.88 ; 2.07,80.72 MH5.1 3.83,82.48 ; J1.4 9.95,65.92 ; J1.4 8.87,67 ; J1.4 7.8,65.92 ; 54.13,115.08 MH4.1 54.13,118.32
  L3 w0.3: MH5.1 4.05,81.6 ; MH5.1 1.85,81.6 ; MH5.1 2.95,82.7 ; MH5.1 2.95,80.5
  L3 w1: 4.69,116.7 MH3.1 2.45,114.58 ; 55.75,114.58 MH4.1 53.12,116.7
  BOTTOM w0.15: 5.49,37.1 P2.2 7.21,38.82 ; 52.91,41.36 P1.3 51.19,39.64 ; 52.91,38.82 P1.2 51.19,37.1 ; 52.07,67.38 52.07,67.55 ; 10.55,77.76 P4.22 12.27,79.48 ; 51.21,67.6 J2.2 52.94,69.32 ; P8.9 2.8,106.95 v1(2.8,106.85) ; 5.49,39.64 P2.3 7.21,41.36 ; 6.35,39.04 6.35,38.85 ; 9.73,66.78 J1.4 8.01,65.06 ; 8.87,64.84 8.87,65 ; 12.49,81.16 12.3,81.16 ; 12.49,78.62 12.3,78.62 ; P8.3 2.01,108.69 1.41,108.69 1.4,108.68 v1(1.32,108.68) ; 7.8,65.92 8,65.92 ; 8.87,67 8.87,66.85 ; 52.05,39.04 52.05,38.85 ; 10.55,80.3 P4.21 12.27,82.02 ; 6.35,36.88 6.35,37.1 ; 11.41,82.24 11.41,82.22 ; 5.27,37.96 5.5,37.96 ; 52.05,36.88 52.05,37.1 ; 6.35,39.42 6.35,39.6
  BOTTOM w0.6: MH5.1 2.95,82.8 ; MH5.1 4.25,81.6 ; MH5.1 1.6,81.6 ; MH5.1 2.95,80.45
  BOTTOM w0.7: J2.2 52.07,69.54 ; J2.2 53.15,68.46 ; J2.2 51,68.46 ; J2.2 52.07,67.55 ; P2.3 7.43,40.5 ; P2.3 6.35,41.58 ; P2.3 5.27,40.5 ; P2.3 6.35,39.6 ; 6.35,38.85 P2.2 ; P2.2 6.35,37.1 ; P2.2 7.43,37.96 ; P2.2 5.5,37.96 ; P1.2 53.13,37.96 ; P1.2 52.05,38.85 ; P1.2 52.05,37.1 ; P1.2 50.97,37.96 ; 8.87,66.85 J1.4 ; J1.4 8,65.92 ; J1.4 9.95,65.92 ; J1.4 8.87,65 ; 50.97,40.5 P1.3 ; P1.3 52.05,39.42 ; P1.3 53.13,40.5 ; P1.3 52.05,41.58 ; 11.41,77.54 P4.22 ; P4.22 P4.21 ; P4.22 10.34,78.62 ; P4.22 12.3,78.62 ; P4.21 12.3,81.16 ; P4.21 11.41,82.22 ; P4.21 10.34,81.16
  vias: v1(0.65,35.45) v1(0.65,31.8) v1(0.72,100.2) v1(0.75,96.95) v1(0.8,92.95) v1(0.79,66.95) v1(0.75,57.3) v1(0.8,51.05) v1(0.7,39.55) v1(0.7,28.95) v1(0.85,98.85) v1(0.85,93.95) v1(0.9,91.5) v1(0.9,69.8) v1(0.83,63.55) v1(0.87,61.35) v1(0.87,47.5) v1(0.85,44.1) v1(0.91,94.99) v1(1.2,85.35) v1(1.55,27.05) v1(1.65,89.95) v1(1.8,37.55) v1(2.05,97.4) v1(2.4,98.8) v1(2.45,65.3) v1(2.45,49.7) v1(2.43,45.4) v1(2.45,40.8) v1(2.55,60.8) v1(2.55,55) v1(2.55,52.65) v1(2.65,68.5) v1(2.65,57.85) v1(2.8,77) v1(3,103.95) v1(3,70.2) v1(3.2,86.9) v1(3.2,31.85) v1(3.15,28.9) v1(3.25,88.65) v1(3.5,85.25) v1(3.5,35.35) v1(3.6,71.5) v1(4,78.5) v1(4.3,75.75) v1(4.25,74) v1(4.65,47.65) v1(4.6,39.05) v1(4.75,86.95) v1(4.75,58.75) v1(4.8,53.6) v1(4.8,51.25) v1(4.95,61.35) v1(5.03,113.3) v1(5.03,111.65) v1(5.07,75.05) v1(5,30.45) v1(5.12,107.52) v1(5.15,106.5) v1(5.15,105.7) v1(5.15,102) v1(5.15,100.65) v1(5.19,97.55) v1(5.1,63.8) v1(5.15,28.25) v1(5.3,89.65) v1(5.25,48.95) v1(5.35,95.1) v1(5.4,94.05) v1(5.63,112.7) v1(5.6,77.05) v1(5.6,42.2) v1(5.95,32.5) v1(6.1,102) v1(6.19,100.9) v1(6.4,96.9) v1(6.35,91) v1(6.35,81.75) v1(6.45,111.85) v1(6.43,99.6) v1(6.65,93.7) v1(6.8,43.4) v1(6.83,84.89) v1(6.95,78.1) v1(7.15,89.5) v1(7.6,92.75) v1(7.65,63.85) v1(7.65,62.15) v1(7.6,56.9) v1(7.6,52) v1(7.65,44.5) v1(7.7,94.9) v1(7.79,84.89) v1(7.7,69.9) v1(7.7,49.55) v1(7.95,26.95) v1(8.19,97.65) v1(8.1,77.4) v1(8.15,40.5) v1(8.25,38.35) v1(8.35,99.55) v1(8.45,91.35) v1(8.5,95.6) v1(8.55,83.4) v1(8.65,109) v1(8.6,93.7) v1(8.6,79.85) v1(8.65,33.4) v1(8.6,29.9) v1(8.85,89.2) v1(9,107) v1(9.05,35.85) v1(9.15,78.15) v1(9.4,43.35) v1(9.6,92.75) v1(9.8,102) v1(9.7,94.9) v1(9.85,107.85) v1(9.85,99.65) v1(9.9,96.95) v1(9.85,71.35) v1(10.05,79.95) v1(10,59.25) v1(10.15,31.55) v1(10.3,56.65) v1(10.3,49.5) v1(10.3,41.15) v1(10.4,46.6) v1(10.45,98.15) v1(10.5,91.55) v1(10.55,67.05) v1(10.55,60.55) v1(10.55,39.25) v1(10.6,52) v1(10.7,93.7) v1(10.79,53.95) v1(10.85,107.02) v1(10.85,90.05) v1(10.9,62.45) v1(10.95,58.3) v1(11,100.8) v1(11,95.6) v1(11,28.65) v1(11.15,70.2) v1(11.25,65.1) v1(11.35,99.6) v1(11.35,85.78) v1(11.35,68.3) v1(11.55,102.1) v1(11.51,82.9) v1(11.65,92.75) v1(11.65,89.1) v1(11.65,35.35) v1(11.87,94.7) v1(11.85,71.35) v1(12.2,105.5) v1(12.2,55.25) v1(12.15,46.15) v1(12.25,98.75) v1(12.25,96.9) v1(12.4,60.75) v1(12.45,68.85) v1(12.5,100.2) v1(12.55,82.65) v1(12.5,58.6) v1(12.55,56.6) v1(12.5,42.4) v1(12.67,79.95) v1(12.6,49.8) v1(12.75,110.75) v1(12.71,83.5) v1(12.75,62.7) v1(12.8,44.65) v1(12.7,39.5) v1(12.95,93.75) v1(12.95,72.6) v1(13.03,86.3) v1(13,66.25) v1(13.15,97.75) v1(13.2,95.7) v1(13.19,64.35) v1(13.25,92.75) v1(13.35,112.7) v1(13.35,71.65) v1(13.4,33.2) v1(13.5,101.2) v1(13.5,99.1) v1(13.59,70.35) v1(13.5,47.55) v1(13.55,29.8) v1(13.5,26.95) v1(13.65,51.25) v1(13.8,55.45) v1(13.7,36.45) v1(13.9,41.1) v1(13.95,61.15) v1(14,110.02) v1(14,67.2) v1(14.1,100.1) v1(14.1,97.25) v1(14.2,58.9) v1(14.15,56.95) v1(14.23,109.31) v1(14.35,72.8) v1(14.35,38.9) v1(14.47,107.93) v1(14.47,105.16) v1(14.45,94.85) v1(14.43,90.75) v1(14.65,50.4) v1(14.75,98.4) v1(14.75,52.4) v1(14.7,48.65) v1(14.95,63.15) v1(15.05,101.5) v1(15,99.5) v1(15,65.6) v1(15.15,79.45) v1(15.15,71.7) v1(15.1,68.3) v1(15.15,54.05) v1(15.23,89.85) v1(15.25,83.4) v1(15.35,60.05) v1(15.45,100.65) v1(15.47,91.85) v1(15.55,95.7) v1(15.55,93.8) v1(15.6,84.65) v1(15.8,97.2) v1(15.7,73.25) v1(15.8,31.95) v1(15.9,55.2) v1(16,57.2) v1(16.15,107.3) v1(16.15,90.75) v1(16.2,64.7) v1(16.15,50.85) v1(16.15,49.85) v1(16.3,48.85) v1(16.3,29.15) v1(16.35,99.5) v1(16.4,61.55) v1(16.43,70.35) v1(16.41,51.82) v1(16.55,118.4) v1(16.55,116.5) v1(16.5,72.35) v1(16.6,100.65) v1(16.6,98.45) v1(16.67,91.9) v1(16.7,94.85) v1(16.71,85.82) v1(16.7,38.25) v1(16.7,35.7) v1(16.85,42.85) v1(16.95,89.8) v1(16.99,60.2) v1(16.95,58.2) v1(17,111.2) v1(17,56) v1(17.05,47.97) v1(17.19,68.35) v1(17.2,63) v1(17.1,49.55) v1(17.27,102.23) v1(17.4,115.4) v1(17.39,83.05) v1(17.45,97.15) v1(17.55,66.85) v1(17.75,107.3) v1(17.75,100.65) v1(17.8,93.75) v1(17.79,90.75) v1(17.75,85.4) v1(17.7,73.25) v1(17.85,91.95) v1(17.9,71.8) v1(18.05,101.5) v1(18.05,99.45) v1(18.05,98.35) v1(18.09,95.4) v1(18,65.05) v1(18.03,57.1) v1(18,37.8) v1(18.05,26.9) v1(18.2,117.4) v1(18.19,59.3) v1(18.3,104.65) v1(18.27,61.05) v1(18.25,49.6) v1(18.39,110.08) v1(18.39,63.05) v1(18.6,36.15) v1(18.8,118.4) v1(18.8,31.45) v1(18.87,70.45) v1(19,34.3) v1(19.15,115.6) v1(19.15,85.45) v1(19.25,72.6) v1(19.3,50.4) v1(19.3,41.9) v1(19.3,40.3) v1(19.35,68.95) v1(19.47,66.85) v1(19.43,63.15) v1(19.43,61.85) v1(19.43,59.95) v1(19.43,58.2) v1(19.43,55.9) v1(19.43,49.6) v1(19.55,51.35) v1(19.5,38.8) v1(19.65,42.95) v1(19.95,109.6) v1(20,83.3) v1(20.2,37.05) v1(20.25,115.95) v1(20.3,46.25) v1(20.3,35.6) v1(20.31,64.85) v1(20.45,73.25) v1(20.45,71.85) v1(20.43,61.15) v1(20.43,56.85) v1(20.47,55.4) v1(20.55,87.5) v1(20.51,63.2) v1(20.51,59.25) v1(20.59,50.1) v1(20.67,105) v1(20.67,44.2) v1(20.85,41.15) v1(20.85,39.65) v1(20.99,93.68) v1(21.15,95.15) v1(21.11,83.49) v1(21.2,70.4) v1(21.2,45.75) v1(21.2,42.9) v1(21.25,110.25) v1(21.27,88.6) v1(21.35,104.35) v1(21.39,56.4) v1(21.4,31.5) v1(21.43,57.7) v1(21.55,36.65) v1(21.55,34.35) v1(21.67,68.8) v1(21.6,29) v1(21.79,64.85) v1(21.83,66.35) v1(21.87,63.5) v1(21.87,58.85) v1(21.91,62.15) v1(21.95,60.5) v1(21.95,46.4) v1(21.99,43.8) v1(22,118.5) v1(22.05,49.6) v1(22.19,45.15) v1(22.1,38.2) v1(22.1,26.95) v1(22.23,95.65) v1(22.23,83.55) v1(22.4,105.4) v1(22.4,103.4) v1(22.47,41.3) v1(22.56,100.6) v1(22.56,99.65) v1(22.5,98.45) v1(22.51,59.45) v1(22.79,47.8) v1(22.8,40.15) v1(22.85,51.5) v1(22.91,42.55) v1(23.03,85.4) v1(23.07,73.15) v1(23.05,57.5) v1(23.15,72) v1(23.1,52.2) v1(23.11,45.75) v1(23.2,37.2) v1(23.15,35.45) v1(23.15,33.45) v1(23.15,28.25) v1(23.3,39) v1(23.25,30.9) v1(23.35,44.25) v1(23.55,114.95) v1(23.55,48.5) v1(23.67,109.95) v1(23.6,91) v1(23.67,46.6) v1(23.8,116.45) v1(23.85,105.85) v1(23.85,89.93) v1(23.95,62.4) v1(24.07,64.8) v1(24,63.45) v1(24.07,41.5) v1(24,27) v1(24.15,70.45) v1(24.19,68) v1(24.1,61.3) v1(24.17,47.75) v1(24.1,39.9) v1(24.3,32.9) v1(24.3,29.3) v1(24.31,66.25) v1(24.31,42.7) v1(24.45,118.55) v1(24.45,34.45) v1(24.51,83.5) v1(24.51,45.25) v1(24.59,44) v1(24.55,36.75) v1(24.6,38.2) v1(24.75,117.45) v1(24.75,89) v1(24.9,100.6) v1(24.9,99.5) v1(24.89,98.35) v1(24.89,97.4) v1(24.89,96.45) v1(24.85,47.1) v1(24.99,62.2) v1(24.95,46.3) v1(24.95,40.55) v1(25,110.05) v1(25.05,87.46) v1(25.05,63.35) v1(25,30.45) v1(25.15,111.4) v1(25.2,107.55) v1(25.2,106.45) v1(25.15,31.95) v1(25.27,95) v1(25.25,28.05) v1(25.4,61.15) v1(25.4,58.35) v1(25.39,48.4) v1(25.4,43.35) v1(25.39,42.2) v1(25.45,59.2) v1(25.55,91.05) v1(25.55,47.7) v1(25.6,72.8) v1(25.65,46.05) v1(25.67,45.15) v1(25.65,35.2) v1(25.8,88.05) v1(25.7,70.6) v1(25.85,118.45) v1(25.9,116.95) v1(25.87,69) v1(25.87,61.95) v1(25.83,48.85) v1(25.85,38.95) v1(25.85,37.7) v1(25.85,36.45) v1(25.95,42.78) v1(26.05,109.55) v1(26.03,67.05) v1(26.03,64.85) v1(26,41.62) v1(26.15,107.55) v1(26.1,44.2) v1(26.15,40.6) v1(26.1,39.6) v1(26.1,26.9) v1(26.23,83.55) v1(26.4,63.45) v1(26.5,34.15) v1(26.5,30.25) v1(26.67,96.35) v1(26.8,114.35) v1(26.75,88.65) v1(26.75,32.8) v1(26.9,35.3) v1(26.9,28.2) v1(26.95,101.8) v1(26.99,100.65) v1(26.99,99.5) v1(27.05,107.55) v1(27.05,106.5) v1(27,71.7) v1(27.03,67.85) v1(27.07,62.5) v1(27.05,31.6) v1(27.15,97.95) v1(27.19,85.32) v1(27.5,113.05) v1(27.55,41.2) v1(27.59,29.35) v1(27.6,89.75) v1(27.63,64.8) v1(27.6,43.2) v1(27.65,42.25) v1(27.75,79.8) v1(27.79,66.15) v1(27.79,63.45) v1(27.8,43.97) v1(27.8,40.33) v1(27.85,115.9) v1(27.83,69) v1(27.83,61.9) v1(27.95,87.5) v1(28,39.17) v1(28,38) v1(28,34.2) v1(28.05,32.45) v1(28,31) v1(28.05,29.95) v1(28.05,28.75) v1(28,27.7) v1(28,26.95) v1(28.25,114.4) v1(28.23,83.55) v1(28.35,70.45) v1(28.4,42.9) v1(28.4,41.65) v1(28.35,36.9) v1(28.41,44.55) v1(28.41,39.8) v1(28.5,40.6) v1(28.8,43.75) v1(28.85,92.8) v1(28.9,74.75) v1(28.87,60.75) v1(28.95,89.7) v1(28.93,45.4) v1(29.03,87.7) v1(29,44.8) v1(29.1,46.35) v1(29.15,42.45) v1(29.2,38.7) v1(29.25,37.65) v1(29.4,113.05) v1(29.35,35.85) v1(29.45,40.8) v1(29.65,118.4) v1(29.65,116.55) v1(29.6,114.45) v1(29.61,83.7) v1(29.75,111.1) v1(29.7,62.75) v1(29.75,45.65) v1(29.75,44.4) v1(29.8,43.3) v1(29.9,68.95) v1(29.85,36.8) v1(29.95,67.6) v1(29.95,41.8) v1(30,91.1) v1(30.05,39.95) v1(30.15,102.25) v1(30.19,99.1) v1(30.1,35.1) v1(30.2,33.75) v1(30.15,31) v1(30.15,29.1) v1(30.15,27.8) v1(30.15,26.9) v1(30.23,93.31) v1(30.4,97.04) v1(30.31,72.9) v1(30.5,78.1) v1(30.5,42.5) v1(30.55,37.8) v1(30.65,36.25) v1(30.7,45.2) v1(30.8,41.4) v1(30.71,28.5) v1(30.95,114.15) v1(30.95,113.1) v1(30.95,74.5) v1(31.05,100.3) v1(31.05,39) v1(31.15,97.05) v1(31.15,46.25) v1(31.23,87.6) v1(31.23,86.5) v1(31.25,40.55) v1(31.3,32.95) v1(31.35,35.6) v1(31.35,34.55) v1(31.45,72.1) v1(31.59,84.95) v1(31.65,44.2) v1(31.65,26.95) v1(31.79,87.1) v1(31.75,30.75) v1(31.9,90.45) v1(31.95,113.1) v1(32.05,39.7) v1(32.2,117.75) v1(32.2,110) v1(32.15,37.8) v1(32.25,41.7) v1(32.31,71.1) v1(32.45,28.9) v1(32.5,34.15) v1(32.67,86.55) v1(32.6,36.5) v1(32.8,118.4) v1(32.71,87.6) v1(32.85,117.17) v1(32.9,114.2) v1(32.9,113.1) v1(32.9,106.25) v1(32.9,100.9) v1(32.9,99) v1(32.9,39.05) v1(33,104.05) v1(33.05,44.15) v1(33.15,70.25) v1(33.3,74.1) v1(33.25,46.1) v1(33.3,32.95) v1(33.4,99.95) v1(33.35,55.9) v1(33.35,40.45) v1(33.47,91.22) v1(33.55,64.3) v1(33.51,62.3) v1(33.59,59.1) v1(33.51,57.95) v1(33.5,35.35) v1(33.5,26.9) v1(33.75,97.05) v1(33.75,65.25) v1(33.79,60.65) v1(33.75,41.75) v1(33.7,36.8) v1(33.8,30.55) v1(33.87,72.25) v1(33.87,69.55) v1(33.95,100.9) v1(33.95,99) v1(33.91,56.75) v1(33.95,38) v1(34.06,82.8) v1(34.2,107.15) v1(34.2,28) v1(34.25,95.7) v1(34.5,34.3) v1(34.67,63.95) v1(34.6,46.1) v1(34.75,97) v1(34.7,56.7) v1(34.75,40.35) v1(34.8,39.05) v1(34.8,36.55) v1(34.9,92.15) v1(34.87,55.55) v1(35.05,95.4) v1(35.08,89.3) v1(35,54.6) v1(35.19,62.15) v1(35.15,58.55) v1(35.2,45.55) v1(35.15,41.75) v1(35.23,68.15) v1(35.25,49.4) v1(35.3,42.8) v1(35.35,29.15) v1(35.4,27) v1(35.5,89.8) v1(35.55,80.55) v1(35.5,32.95) v1(35.65,114.75) v1(35.65,53.95) v1(35.75,56.75) v1(35.8,48.85) v1(35.75,37.45) v1(35.8,35.45) v1(35.87,55.2) v1(35.95,94.75) v1(35.95,74.55) v1(35.99,63.6) v1(36.05,94.05) v1(36.1,92.3) v1(36,72.95) v1(36.07,65.3) v1(36.03,60.7) v1(36.05,44.75) v1(36.25,106.75) v1(36.25,84.1) v1(36.25,40.35) v1(36.5,43.35) v1(36.63,99.85) v1(36.65,89) v1(36.7,89.95) v1(36.79,59.1) v1(36.71,57.6) v1(36.79,55.65) v1(36.79,54.15) v1(36.7,46.3) v1(36.7,41.85) v1(36.7,30.65) v1(36.9,103.8) v1(36.9,36.6) v1(36.85,34.4) v1(36.95,104.8) v1(36.95,102.4) v1(36.95,39.05) v1(37.3,45.2) v1(37.25,28) v1(37.45,116.85) v1(37.59,62.15) v1(37.71,99.6) v1(37.75,98.9) v1(37.79,64.25) v1(37.79,49.05) v1(37.9,37.7) v1(37.9,35.6) v1(38,89.85) v1(38,60.55) v1(38.07,54.05) v1(38,32.95) v1(38.2,109.75) v1(38.11,55.35) v1(38.15,43.35) v1(38.15,41.55) v1(38.15,29.3) v1(38.27,78.35) v1(38.32,87.72) v1(38.35,46.15) v1(38.47,56.95) v1(38.55,27.05) v1(38.65,92.25) v1(38.63,83.15) v1(38.6,39.6) v1(38.7,113.6) v1(38.8,108.9) v1(38.9,98.6) v1(38.85,34.65) v1(38.99,104) v1(38.95,80.9) v1(39.07,89.85) v1(39.03,63.5) v1(39.05,36.7) v1(39.1,116.75) v1(39.15,42.55) v1(39.23,59) v1(39.25,44.75) v1(39.25,30.7) v1(39.31,49.35) v1(39.67,54.65) v1(39.75,113.65) v1(39.8,46.3) v1(39.7,40.9) v1(39.85,112.15) v1(39.85,97.7) v1(39.9,39.1) v1(40.03,75.2) v1(40.07,62.2) v1(40.03,60.55) v1(40.15,77) v1(40.15,43.2) v1(40.4,36.05) v1(40.43,56.45) v1(40.65,116.8) v1(40.6,88.4) v1(40.65,32.9) v1(40.7,58.35) v1(40.7,37.65) v1(40.83,65.35) v1(40.95,96.55) v1(40.99,63.9) v1(41.08,113.65) v1(41,69.5) v1(41.07,54.3) v1(41.03,49.05) v1(41,27.4) v1(41.15,100.15) v1(41.1,94.45) v1(41.2,89.95) v1(41.23,106.2) v1(41.23,45.8) v1(41.25,44.45) v1(41.31,104.1) v1(41.51,115.75) v1(41.59,79.88) v1(41.65,30.45) v1(41.88,116.7) v1(42.05,70.55) v1(42.2,55) v1(42.19,37.7) v1(42.23,46.25) v1(42.3,28.8) v1(42.39,63.5) v1(42.39,62.15) v1(42.39,60.45) v1(42.35,59.1) v1(42.31,57.15) v1(42.43,64.8) v1(42.59,103.75) v1(42.59,98.5) v1(42.9,96) v1(42.85,95.05) v1(42.87,71.75) v1(43,34.6) v1(43,27.05) v1(43.15,108.8) v1(43.15,88.38) v1(43.3,110.95) v1(43.3,69.3) v1(43.3,36.6) v1(43.25,30.2) v1(43.35,46.9) v1(43.35,41.95) v1(43.5,117.25) v1(43.55,33.4) v1(43.85,101.35) v1(43.95,41.45) v1(44.2,108.45) v1(44.15,98.55) v1(44.11,71.75) v1(44.35,45.1) v1(44.45,88.38) v1(44.8,117.65) v1(44.75,91) v1(44.79,48.55) v1(44.79,47.05) v1(44.7,32) v1(45.03,94.5) v1(45.2,110.5) v1(45.2,98.55) v1(45.11,37.6) v1(45.25,41.45) v1(45.35,115.6) v1(45.39,45.5) v1(45.43,80.1) v1(45.45,70.55) v1(45.51,107.65) v1(45.6,31) v1(45.75,109.15) v1(45.75,27.05) v1(45.85,101.2) v1(45.83,91.8) v1(45.87,38.75) v1(45.85,36.3) v1(45.91,40.25) v1(46.05,69.3) v1(46.19,48.75) v1(46.39,47.2) v1(46.47,90.95) v1(46.5,111.8) v1(46.5,71.7) v1(46.55,50.25) v1(46.59,44.8) v1(46.63,94.7) v1(46.67,42.35) v1(46.85,98.5) v1(46.95,103.75) v1(47.1,101.15) v1(47.19,80.15) v1(47.25,40.3) v1(47.27,37.3) v1(47.4,110.3) v1(47.35,108.5) v1(47.35,33.35) v1(47.5,35.75) v1(47.67,81.9) v1(47.65,30.5) v1(47.7,73.8) v1(47.75,71.15) v1(47.71,46.1) v1(47.85,69.25) v1(47.95,94.74) v1(47.95,38.6) v1(47.95,28.3) v1(48,118.45) v1(48.1,98) v1(48.15,44.05) v1(48.3,86.5) v1(48.27,42.35) v1(48.31,53.75) v1(48.43,52.5) v1(48.6,117.7) v1(48.79,40.2) v1(48.83,37.45) v1(49.05,104.75) v1(49.05,59.5) v1(49.07,35.8) v1(49.2,107.05) v1(49.2,95.6) v1(49.1,70.2) v1(49.2,34.05) v1(49.28,94.9) v1(49.4,31.75) v1(49.55,41.25) v1(49.65,28.95) v1(49.75,76.9) v1(49.75,74.3) v1(49.85,99.95) v1(49.9,42.4) v1(50,117.25) v1(50,106.45) v1(50.03,39.25) v1(50.03,34.8) v1(50.39,88.45) v1(50.39,43.75) v1(50.43,89.65) v1(50.7,97.3) v1(50.8,64.55) v1(50.85,75.45) v1(50.85,67) v1(50.95,59.9) v1(51.05,85.4) v1(51.1,112.65) v1(51.25,113.95) v1(51.3,27.05) v1(51.43,83.15) v1(51.65,74.15) v1(51.7,112) v1(51.75,111) v1(51.7,109) v1(51.8,80) v1(51.7,32.85) v1(51.85,99) v1(52,72.05) v1(52.1,70.75) v1(52.15,43.6) v1(52.25,76.7) v1(52.4,118.1) v1(52.4,30.6) v1(52.45,104.1) v1(52.45,103.45) v1(52.6,105.4) v1(52.85,114.1) v1(52.95,108.75) v1(53,101.05) v1(53.05,86.55) v1(53.03,74.6) v1(53.1,110.05) v1(53.11,92.2) v1(53.1,88.35) v1(53.15,81.05) v1(53.15,27.5) v1(53.4,112.25) v1(53.45,42.65) v1(53.55,104.4) v1(53.59,87.3) v1(54.03,86.55) v1(54.05,28.85) v1(54.2,105.4) v1(54.1,99) v1(54.15,88.4) v1(54.25,103.5) v1(54.25,97.5) v1(54.3,82.45) v1(54.3,53.05) v1(54.3,49.9) v1(54.23,46.85) v1(54.35,56.85) v1(54.35,44) v1(54.4,38.2) v1(54.45,33.95) v1(54.55,41.15) v1(54.65,109.5) v1(54.7,83.9) v1(54.8,68.6) v1(54.7,61.5) v1(54.85,78.25) v1(54.85,65.55) v1(55,81) v1(55.05,31.9) v1(55.27,74.85) v1(55.4,35.35) v1(55.7,96.35) v1(55.71,72.7) v1(55.7,29.1) v1(55.9,99.15) v1(55.9,79.25) v1(56.05,111.65) v1(56.1,94.85) v1(56.05,91.75) v1(56.1,82.95) v1(56.15,89.05) v1(56.2,27.05) v1(56.25,84.14) v1(56.55,106.95) v1(56.7,96.2) v1(56.85,35.5) v1(56.95,84.7) v1(57,81.45) v1(57.2,113.45) v1(57.2,107.25) v1(57.11,58.35) v1(57.15,53.2) v1(57.25,103.15) v1(57.3,99.2) v1(57.31,62.25) v1(57.35,47.6) v1(57.35,45) v1(57.3,42.6) v1(57.31,40.15) v1(57.35,37.15) v1(57.4,28.65) v1(57.45,94.75) v1(57.45,85.95) v1(57.45,64.25) v1(57.45,60.25) v1(57.45,56.25) v1(57.45,50.25) v1(57.45,32.95) v1(57.5,97.05) v1(57.55,69.5) v1(57.5,67.35) v2(27.38,54.15) v2(27.38,53.15) v2(27.38,52.15) v2(27.38,51.15) v2(27.38,50.15) v2(28.38,54.15) v2(28.38,53.15) v2(28.38,52.15) v2(28.38,51.15) v2(28.38,50.15) v2(29.38,54.15) v2(29.38,53.15) v2(29.38,52.15) v2(29.38,51.15) v2(29.38,50.15) v2(30.38,54.15) v2(30.38,53.15) v2(30.38,52.15) v2(30.38,51.15) v2(30.38,50.15) v2(31.38,54.15) v2(31.38,53.15) v2(31.38,52.15) v2(31.38,51.15) v2(31.38,50.15)
